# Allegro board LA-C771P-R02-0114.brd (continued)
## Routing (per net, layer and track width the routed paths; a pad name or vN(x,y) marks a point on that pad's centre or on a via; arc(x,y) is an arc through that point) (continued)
+1.8VALW: length 342.5
  TOP w0.305: v3(119.49,72.55) RC81.2
  TOP w0.381: CW4.1 99.98,15.5 99.89,15.59 UW2.1
  TOP w0.508: 50.2,70.6 49.49,71.31 48.34,71.31 48.19,71.15 48.18,71.15 47.62,70.59 47.62,70.58 47.56,70.52 47.56,68 47.17,67.62 47.17,64.68 51.25,60.6 52.49,60.6 55.19,57.9 55.19,57.72 55.19,57.35 58.88,53.66 58.88,48.12 58.25,47.48 v3(57.41,47.48) 56.45,47.48 55.66,48.27 RC52.1 ; 122.69,72.57 125,70.26 125,63.23 137.78,50.45 v3(139,50.45) ; 122.69,72.57 123.22,73.11 123.22,73.75 122.29,74.68 RC28.2 121.07,74.53 RC29.2 ; 122.69,72.57 v3(122.03,72.57) ; v3(57.01,46.28) 57.25,46.28 57.67,45.86 RC50.1 ; CC22.1 56.04,38.87 55.53,39.38 55.07,39.38 54.83,39.14 UC10.8 ; CC22.1 56.45,38.9 56.45,39.15 57.31,40.01 RC51.1 60.74,40.27 66.2,34.81 72.8,34.81 75.03,32.58 v3(75.03,32.27) RB13.1 ; CC22.1 56.42,38.26 v3(56.22,38.06) ; 87.92,32.5 87.92,31.12 88.12,30.92 88.12,29.12 QC2.2 ; 87.92,32.5 88.73,33.31 v2(91.96,33.31) 97.9,33.31 100.38,30.83 v3(101.6,30.83) 102.27,30.16 102.27,17.36 v3(102.32,17.31) 101.85,17.31 101.6,17.05 RW5.1 101.6,16.47 100.97,15.84 100.97,15.71 100.96,15.7 CW4.1 ; 87.92,32.5 87.53,32.89 87.53,33.55 87,34.07 85.35,34.07 82.68,31.4 v3(82.68,30.84) 82.57,30.73 82.57,29.9 83.52,28.96 RB7.2 ; v3(157.89,37.98) 160.82,37.98 161.7,37.09 v3(169.56,37.09) ; RW8.1 v3(93.88,17.15)
  IN1 w0.508: v3(157.89,37.98) 157.89,37.98 157.89,38.35 150.41,45.83 144.33,45.83 139.71,50.45 v3(139,50.45)
  IN2 w0.305: v3(119.49,72.55) 119.49,72.62 119.94,73.08 120.94,73.08 121.44,72.57 v3(122.03,72.57)
  IN2 w0.508: v3(102.32,17.31) 102.32,17.28 102.19,17.15 v3(93.88,17.15) ; v3(157.89,37.98) 158.88,36.99 158.88,29.2 155.35,25.66 154.67,25.66 v3(154.59,25.59) ; v3(57.41,47.48) 57.01,47.08 v3(57.01,46.28) ; v3(75.03,32.27) 75.64,31.66 81.87,31.66 v3(82.68,30.84)
  BOTTOM w0.229: UC4.AA18 107.3,82.38 107.3,82.93 106.71,83.52 v3(106.71,84.71)
  BOTTOM w0.254: UC4.N20 103.4,80.52 v3(103.4,80.37)
  BOTTOM w0.305: RC59.1 90.62,84.13 v3(91.22,84.13) 91.78,84.13 RC61.1
  BOTTOM w0.508: RM19.2 170.21,79.54 169.56,78.88 v3(169.56,37.09) ; v3(87.91,84.34) 88.16,84.59 RC38.1 ; v3(57.01,46.28) 55.84,45.11 55.84,38.43 v3(56.22,38.06) ; v3(154.59,25.59) 152.64,25.59 151.37,24.32 126.86,24.32 120.64,30.53 102.59,30.53 102.29,30.83 v3(101.6,30.83) ; CC61.1 95.8,82.56 v3(96.18,82.94) ; RC36.2 90.5,85.38 90.5,85.37 v3(91.07,85.37) 91.69,85.37 RC35.1
  vias: v3(51.34,70.7) v3(51.37,70.09) v3(51.37,69.48) v3(72.39,75.01) v3(72.41,74.36) v3(72.39,73.69) v3(73.04,73.69) v3(73.12,75.01) v3(73.07,74.36) v3(85.43,79.89) v3(86.14,79.89) v3(86.24,81.67) v3(86.85,81.67) v3(95.71,83.4) v3(104.78,78.42)
+1.8VALWP: length 5.3
  TOP w0.254: 69.05,71.06 69.05,70.9 68.49,70.34 v2(68.43,70.34) 66.29,70.34 65.49,71.14 PC604.1 PR603.1
+1.8VS: length 280.9
  TOP w0.381: v3(81.31,71.34) 82.67,69.98 88.28,69.98 88.83,69.43 v3(89.09,69.43) 91.84,72.18 97.88,72.18 98.84,73.14 102.2,73.14 RC9.2 102.87,73.25 104.64,73.25 104.91,72.98 v3(104.91,72.6) ; 18.12,95.97 18,96.08 14.82,96.08 14.47,95.73 14.47,95.19 14.03,94.75 RY2.1
  TOP w0.508: v3(60.22,81.15) 59.98,80.9 55.23,80.9 v3(55.08,81.06) ; 130.54,74.59 130.56,74.56 130.56,66.2 v3(129.88,65.51) ; v3(114.53,71.74) 114.54,71.73 114.54,68.69 v3(114.46,68.61) ; v3(81.31,71.34) 81.53,71.56 UC7.5 ; v3(126.19,74.56) 123.91,74.56 122.01,76.46 RC21.1 ; v3(74.69,75.3) 74.8,75.19 75.69,75.19 76.79,76.29 UC8.5
  TOP w0.762: 129.34,91.6 128.43,91.6 127.97,92.06 125.84,92.06 124.67,90.89 124.67,87.21 128.5,83.37 v3(128.5,81.18) 128.5,78.65 130.54,76.62 130.54,74.59 v3(130.54,74.59)
  IN1 w0.406: 112.91,68.06 112.1,68.06 111.16,69 111.16,69.68 110.17,70.67 109.58,70.67 108.19,72.07 106.74,72.07 106.65,71.98 105.4,71.98 104.88,72.5 104.88,72.6 v3(104.91,72.6) ; 112.91,68.06 112.99,68.06 113.55,68.61 v3(114.46,68.61) ; 112.91,68.06 112.91,67.32 114.92,65.31 117.27,65.31 117.98,64.6 120.8,64.6 121.23,65.03 v3(123.81,65.03)
  IN1 w0.508: v3(129.88,65.51) 126.04,65.51 125.56,65.03 v3(123.81,65.03) ; v3(130.54,74.59) 130.31,74.59 129.83,75.07 126.42,75.07 126.19,74.84 v3(126.19,74.56)
  IN1 w1.016: 23.91,93.63 24.87,94.6 35.01,94.6 37.17,96.76 49.97,96.76 52.31,94.42 52.31,91.65 51.19,90.53 v3(51.19,88.5) 52.28,87.41 55.23,87.41 57,85.63 ; 121.37,100.67 87.22,100.67 84.09,97.54 78.01,97.54 74.84,94.37 72.17,94.37 71.56,93.76 71.56,91.2 69.92,89.56 66.17,89.56 65.37,88.76 62.19,88.76 60.16,86.72 58.1,86.72 57,85.63 ; 57,85.63 57,84.9 54.62,82.51 54.62,82.03
  BOTTOM w0.254: UC4.U38 105.34,72.17 v3(104.91,72.6) ; RPY1.3 18.05,89.59 18.05,90.09 18.19,90.23 v3(18.75,90.23) 18.77,90.22 18.77,90.04 18.55,89.82 RPY1.4
  BOTTOM w0.508: RX3.1 50.25,88.09 50.66,88.5 v3(51.19,88.5) ; v3(55.08,81.06) 54.91,80.9 UC5.5 ; RC22.1 125.51,74.74 125.58,74.81 RC79.2 125.94,74.81 v3(126.19,74.56) ; v3(123.81,65.03) CC71.1 CC70.1 CC69.1 CC74.1 ; UC6.5 v3(60.22,81.15) ; v3(128.5,81.18) 128.33,81.36 RC82.2 ; v3(89.09,69.43) 89.14,69.48 CC67.1 ; RC14.1 91.3,75.09 85.06,75.09 v3(81.31,71.34) 78.83,71.34 74.88,75.3 v3(74.69,75.3)
  vias: v2(31.96,48.99) v3(18.83,95.72) v3(18.83,95.13) v3(22.39,92.9) v3(22.97,92.87) v3(23.78,32.39) v3(24.37,32.55) v3(32.82,22.79) v3(33.4,22.79) v3(54.41,76.13) v3(55.1,76.16) v3(114.34,74.79) v3(122.47,100.5) v3(123.24,100.5) v3(129.42,88.34) v3(129.39,87.66)
+1.8VS_AVDD2: length 4.6
  TOP w0.203: UA1.40 29.4,23.48 v3(29.47,23.4)
  TOP w0.508: v3(29.47,23.4) 29.47,23.28 30.01,22.74 CA9.1 30.77,22.74 RA5.1
+1.8VS_OUT:
  vias: v2(55.71,70.35)
+1.35V: length 119.1
  TOP w0.635: RD1.1 69.15,50.93 68.42,51.66 61.95,51.66 55.94,57.67 55.94,58.56 51.8,62.7 51.8,63.74
  TOP w1.016: RD1.1 77.41,48.18 79.74,50.5 90.03,50.5
  BOTTOM w0.254: v3(97.52,43.49) 98.02,43.49 98.48,43.95 98.48,45.37 98.93,45.82 JDIMM1.99
  BOTTOM w0.305: v3(103.08,44.51) 102.53,45.05 102.53,45.81 102.53,45.82 JDIMM1.111 ; JDIMM1.88 v3(95.63,39.98) ; v3(94.95,44.43) 95.1,44.43 95.49,44.81 95.49,45.58 95.33,45.73 JDIMM1.87 ; v3(97.43,39.95) JDIMM1.94 ; v3(106.13,40.64) 106.13,40.59 106.43,40.29 JDIMM1.124 ; 97.13,44.92 96.93,44.71 v3(96.43,44.71) ; 97.13,44.92 JDIMM1.93 ; 97.13,44.92 97.31,44.73 v3(97.62,44.73) ; v3(104.44,44.1) 104.37,44.1 103.92,43.65 103.92,43.19 103.38,42.65 v3(103.38,40.82) 102.83,40.27 JDIMM1.112 ; JDIMM1.75 91.73,45.78 90.51,44.56 v3(89.97,44.56)
  BOTTOM w0.356: v3(104.63,40) JDIMM1.118 ; v3(96.75,41.66) 98.41,41.66 99.23,40.84 JDIMM1.100 ; v3(106.61,45.22) 106.13,45.7 JDIMM1.123 ; JDIMM1.82 93.83,40.19 93.33,40.7 v3(93.22,40.7) 93,40.7 92.39,41.31 92.39,41.69 92.79,42.1 v3(93.1,42.1) ; JDIMM1.105 100.73,45.52 100.31,45.1 100.31,43.77 99.89,43.35 99.56,43.35 v3(99.55,43.36) ; v3(92.44,44.63) 92.69,44.63 93.53,45.47 JDIMM1.81 ; JDIMM1.117 104.33,45.41 104.3,45.38 v3(104.3,45.34) ; v3(95.64,41.36) 95.21,41.36 94.7,41.87 94.7,44.18 v3(94.95,44.43) ; v3(91.37,40.67) 91.6,40.67 92.03,40.24 JDIMM1.76 ; v3(100.87,40.26) 100.87,40.21 101.03,40.05 JDIMM1.106
  BOTTOM w0.508: RC6.1 117.89,61.19 117.49,60.79 117.49,60.44 CC31.2 116.82,60.44 CC32.2 116.8,59.98 117.13,59.65 117.13,56.52 122.56,51.09 v3(122.56,51.1)
  vias: v2(122.17,34.79) v3(93.07,35.95) v3(93.78,34.57) v3(94.77,35.92) v3(95.89,34.5) v3(96.98,35.87) v3(97.9,34.42) v3(99.04,35.31) v3(99.85,34.5) v3(101.02,35.26) v3(101.76,34.32) v3(102.62,35.26) v3(103.74,34.45) v3(104.73,35.31) v3(138.34,39.3) v3(138.34,38.54) v3(138.34,37.78) v3(138.34,37.01) v3(138.39,34.11) v3(138.39,33.34) v3(138.39,32.58) v3(138.39,31.82) v3(139.1,39.3) v3(139.1,38.54) v3(139.1,37.78) v3(139.1,37.01) v3(139.16,34.11) v3(139.16,33.34) v3(139.16,32.58) v3(139.16,31.82)
+1.35V_SOC: length 31.7
  IN2 w0.508: v3(120.1,68.67) 119.53,69.25 118.63,69.25 116.85,71.03 113.52,71.03 112.83,71.72 112.81,71.72 v3(112.81,71.71)
  BOTTOM w0.254: v3(98.97,66.34) 98.97,65.84 UC4.C51 ; v3(118.57,66.45) 118.95,66.83 UC4.BD49 ; UC4.A48 97.3,67.16 v3(97.19,67.04) ; UC4.F49 100.36,66.88 v3(100.77,67.29) ; UC4.F52 100.36,65.08 UC4.F53 100.36,64.1 v3(99.89,63.63) ; v3(118.72,63.76) 118.72,64.41 UC4.BD53 118.94,65.08 UC4.BD52 ; UC4.AV41 UC4.AV42 115.98,69.83 v3(115.57,69.42) ; UC4.BG51 120.27,65.78 v3(119.75,65.78) ; UC4.H46 101.71,68.69 v3(101.83,68.69) ; UC4.BB46 117.62,68.33 117.5,68.2 117.5,68.18 v3(117.49,68.18) ; UC4.D44 99.74,68.88 v3(99.74,68.63) ; UC4.AK38 112.4,72.1 112.81,71.69 112.81,71.71 ; v3(122.53,67.13) 122.51,67.16 UC4.BJ48 ; UC4.AM38 113.18,72.08 112.81,71.71 ; UC4.BF44 119.82,68.96 v3(120.1,68.67) ; 112.81,71.71 v3(112.81,71.71)
  BOTTOM w0.381: CC36.2 92.64,66.43 v3(92.62,66.45) ; CC35.2 99.7,59.47 v3(99.85,59.61) ; RC69.2 120.94,60.66 120.94,63.07 v3(121.19,63.33)
  BOTTOM w0.508: CC33.2 119.46,61.98 118.72,62.73 v3(118.72,63.76) ; v3(122.53,67.13) 123.62,66.05 CC34.2
  vias: v3(102.82,70.15) v3(107.73,71.48)
+1.35VP: length 46
  TOP w0.508: v3(141.92,38.85) v2(146.4,38.85) 154.54,38.85 155.81,37.58 155.81,36.79 159.11,33.49 159.11,27.92 157.98,26.79 PR406.1
  IN2 w0.254: v3(154.68,33.85) 154.95,34.13 154.95,36.26 152.97,38.23 143.09,38.23 v3(142.5,37.64)
  BOTTOM w0.254: PR407.2 v3(154.68,33.85) 154.47,33.65 PU303.5
+1.35VS: length 84.2
  TOP w0.381: v3(107.3,79.35) 107.5,79.35 108.18,80.04 CC42.1 ; v3(109.67,81.61) 109.88,81.83 CC41.1 109.88,83.25 CC40.1
  TOP w0.508: v3(91.26,95.33) 91.26,96.57 93.81,99.12 104.55,99.12
  IN1 w0.508: v3(89.89,93.23) 92.17,93.23 92.97,92.42 92.97,89.33 92.2,88.56 92.2,85.1 92.31,85
  IN1 w0.762: 54.47,63.86 54.47,64.59 56.14,66.26 56.14,69.28 56.65,69.78 57.33,69.78 61.7,74.15 62.63,74.15 67.57,79.09 68.6,79.09 71.2,81.7 73.76,81.7 74.79,82.73 81.22,82.73 81.83,83.34 85.5,83.34 87.54,85.38
  BOTTOM w0.203: UC4.AA25 107.3,78.6 v3(107.3,79.35)
  BOTTOM w0.254: v3(108.86,73.25) 109.21,72.9 UC4.AD36 ; v3(110.44,74.8) 110.81,75.18 UC4.AG32 ; UC4.U36 105.35,72.9 v3(105.73,73.29) UC4.V36
  BOTTOM w0.508: CC48.1 105.88,91.57 v3(106.02,91.57) ; v3(91.26,95.33) 90.58,94.65 RC43.1 90.01,94.5 89.7,94.18 89.7,93.42 v3(89.89,93.23) ; CC47.1 92.95,82.97 CC49.1 94.43,82.97 v3(94.47,83.01)
  vias: v2(115.2,99.46) v3(54.16,62.77) v3(54.74,62.77) v3(107.76,90.93) v3(108.23,90.51) v3(120.6,95.05) v3(121.28,95.02)
+1.35VS_OUT:
  vias: v2(54.34,66.35)
+3V_HDD: length 9.2
  BOTTOM w0.102: v2(208.57,45.75) 208.76,45.56 JHDD1.9 ; JHDD1.8 208.86,44.29 v2(208.49,43.93) ; v2(208.52,47.52) 209.2,46.83 JHDD1.10
+3V_HUB: length 17.9
  TOP w0.254: US2.20 194.95,55.41 CS9.1
  TOP w0.508: RS14.1 RS12.1 188.73,57.98 v3(188.68,57.92) 188.27,57.92 187.87,57.51 v2(187.87,57.21) 187.87,54.87 188.25,54.49 189.01,54.49 189.59,55.08 RS13.1 ; CS9.1 195.49,55.38 v3(195.49,55.91)
  IN1 w0.508: v3(195.49,55.91) 194.42,56.98 192.01,56.98 191.07,57.92 v3(188.68,57.92)
+3V_LAN: length 1.8
  BOTTOM w0.203: v3(34.68,71.66) 35.07,71.27 UL1.11
  BOTTOM w0.508: v3(38.44,62.59) 38.72,62.87 RL4.2
  vias: v2(37.8,64.52) v3(32.31,65.08) v3(32.95,65.22) v3(33.99,72.32) v3(33.97,71.71) v3(38.62,67.19) v3(38.82,67.75)
+3VALW: length 288.3
  TOP w0.508: v3(201.02,96.02) v2(201.02,93) 201.02,89.27 v3(199.93,88.17) ; RC27.2 83.31,78.39 v3(82.79,78.92) ; v3(71.41,32.27) 71.29,32.15 RB27.1 ; v3(69.07,32.77) 68.93,32.63 RB2.1 ; v3(85.86,29.46) 85.86,26.68 86.57,25.97 v3(86.57,25.03) ; v3(73.6,78.68) 73.6,78.68 73.6,81.17 75.29,82.85 77.15,82.85 v2(78.62,84.33) 79.39,85.1 84.74,85.1 87.56,87.92 87.56,89.95 88.93,91.32 88.93,94.23 89.22,94.51 92.59,94.51 92.89,94.81 v3(92.89,95.25) 92.89,96.42 94.26,97.8 100.68,97.8 101.25,97.23 RC76.2
  IN1 w0.508: 158.45,58 151.16,58 150.6,58.56 150.6,62.65 149.79,63.46 v3(148.87,63.46) ; 158.45,58 159.98,58 160.61,58.63 160.61,62.12 161.95,63.46 v3(162.79,63.46) ; 158.45,58 158.45,53.03 161,50.48 168.31,50.48 174.23,56.4 174.23,86.79 175.06,87.61 181.03,87.61 182.76,89.34 192.06,89.34 198.74,96.02 v3(201.02,96.02)
  IN1 w1.016: 33.84,89.04 37.24,89.04 39.99,91.78 39.99,94.01 41.46,95.49 43.98,95.49 46.85,92.62 46.85,88.76 48.78,86.83 49.74,86.83 51.45,85.12 51.45,78.33 52.97,76.81 52.97,76.71 52.97,76.45 52.97,76.45 52.97,73.82 55.13,71.66 55.13,66.68 53.27,64.83 53.27,61.3 ; v3(199.93,88.17) 199.93,87.97 205.62,82.28 205.62,69.02 203.64,67.04 203.64,60.66 207.83,56.47 207.83,48.22
  IN2 w0.508: v3(85.86,29.46) 85.86,29.7 85.45,30.11 84.11,30.11 83.43,29.43 74.92,29.43 72.09,32.27 v3(71.41,32.27) 71.13,31.99 70.11,31.99 69.33,32.77 v3(69.07,32.77)
  BOTTOM w0.381: v3(92.89,95.25) 93.14,95 UC9.5
  BOTTOM w0.508: PR729.2 149.62,63.46 149.62,63.46 v3(148.87,63.46) ; PR712.1 162.79,63.46 v3(162.79,63.46)
  vias: v2(59.04,56.57) v3(32.85,88.93) v3(32.82,88.3) v3(57.18,58.61) v3(57.19,58.02) v3(57.82,58.61) v3(57.82,57.97) v3(58.45,58.58) v3(58.48,57.97) v3(72.24,77.99) v3(72.26,78.64) v3(72.95,78.62) v3(72.92,77.97) v3(73.6,77.97) v3(189.44,23.68) v3(189.44,22.31) v3(189.46,22.97) v3(189.47,21.62) v3(190.15,23.68) v3(190.15,22.97) v3(190.15,22.31) v3(190.15,21.62) v3(190.86,23.63) v3(190.86,22.97) v3(190.86,22.28) v3(190.86,21.62) v3(198.97,88.32) v3(202.47,14.87) v3(203.11,14.87) v3(203.74,14.87) v3(204.33,14.87) v3(205.68,40.51) v3(205.68,39.85) v3(205.7,39.17) v3(205.68,38.5) v3(205.68,37.84) v3(205.7,37.18) v3(205.68,36.44) v3(206.44,40.51) v3(206.44,39.85) v3(206.41,39.16) v3(206.44,38.5) v3(206.44,37.84) v3(206.44,36.44) v3(206.46,37.18)
+3VALW_EC: length 59.9
  TOP w0.508: RW3.1 92.06,17.13 91.62,16.69 91.62,15.91 v3(91.42,15.71) ; 83.97,21.21 84.73,21.98 85.76,21.98 85.96,22.18 v3(85.96,23.07) 86.37,23.07 86.7,22.74 86.7,20.69 87.94,19.44 87.94,16.92 87.71,16.69 87.71,15.93 v3(87.56,15.78) ; 83.97,21.21 RB5.2 ; 83.97,21.21 84.52,20.67 84.52,19.77 83.72,18.98 RB20.2 ; RB18.1 69.83,31.58 68.93,30.67 RB2.2 68.93,30.64 ; v3(81.69,15.32) 81.69,15.07 82.76,14 RB21.2
  IN2 w0.508: v3(85.96,23.07) 85.93,23.07 85.84,22.97 80.37,22.97 79.89,22.48 77.91,22.48 76.56,21.14 74.99,21.14 74.43,20.58 72.17,20.58 70.39,22.36 68.95,22.36 66.83,24.48 65.75,24.48 64.75,25.48 64.75,27.87 v3(63.18,29.45)
  BOTTOM w0.508: v3(81.69,15.32) 82,15.63 87.41,15.63 v3(87.56,15.78) 87.84,16.06 89.92,16.06 90.28,15.71 v3(91.42,15.71)
  vias: v2(78.41,5.46) v3(53.91,32.24) v3(53.93,31.58) v3(62.47,30.06)
+3VALW_SOC: length 19.5
  TOP w0.305: v3(104.04,80.38) 104.04,80.98 CC81.1 103.99,81.1 103.99,82.25 104.03,82.29 v3(104.03,82.3) 104.13,82.39 104.13,83.77 103.42,84.48 103.42,85.99 103.33,86.08 103.33,87.29
  TOP w0.508: 103.33,87.29 103.06,87.56 103.06,89.77 103.28,89.99 v2(103.28,93.51) 103.16,93.63 103.16,94.29 103.28,94.42 CC83.1 CC79.1 101.26,95.18 RC76.1
  BOTTOM w0.254: v3(104.04,80.38) 104.04,80.18 UC4.N22
  BOTTOM w0.381: UC4.N18 103.74,82.01 v3(104.03,82.3) 104.45,81.87 UC4.P18
+3VALWP: length 27.3
  TOP w0.508: v2(189.9,42.86) 189.9,42.05 v3(189.99,41.96)
  IN2 w0.254: v3(201.55,40.79) 201.55,40.8 200.41,41.94 193.86,41.94 193.39,42.41 190.88,42.41 190.42,41.96 v3(189.99,41.96)
  IN2 w0.381: v3(201.47,39.92) 199.97,41.43 193.61,41.43 193.07,41.97 191.14,41.97 190.69,41.52 190.69,41.08 v3(190.82,40.95)
  BOTTOM w0.254: PR302.2 v3(189.99,41.96) ; v3(190.82,40.95) 190.91,40.86 PU301.4
+3VDD_CODEC: length 11.8
  TOP w0.203: UA1.36 26.97,21.08 27.22,20.84 v3(27.97,20.84)
  IN2 w0.508: v3(27.97,20.84) 27.97,21.09 26.96,22.11 26.96,27.81 v3(27.69,28.54)
  BOTTOM w0.508: v3(27.97,20.84) 28.54,20.27 29.62,20.27 CA18.2
+3VLP: length 526.9
  TOP w0.203: UB1.111 80.99,19.37 81.18,19.56 ; UA1.20 20.82,23.88 v3(20.73,23.79)
  TOP w0.508: v3(166.78,38.24) 176.33,38.24 v2(178.26,40.17) 178.26,59.62 v3(182.41,63.76) ; 81.18,19.56 81.52,19.9 82.42,19.9 CB7.1 v3(82.5,20.5) ; v3(86.58,29.51) 86.51,29.43 86.51,26.93 87.42,26.02 87.42,20.88 88.58,19.72 v3(88.58,19.29) 88.58,16.66 88.35,16.43 88.35,15.22 92.77,10.8 94.75,10.8 95.71,9.84 v3(95.71,8.87) ; v3(79.05,2.96) 79.54,3.44 79.54,6.11 82.07,8.65 RB4.1 ; v3(166.78,28.76) 166.01,28.76 v3(157.45,20.2) ; R7.2 v3(21.49,7.12) ; v3(189.09,41.92) 189.09,41.74 190.58,40.24 PR314.1 ; R3.2 28.76,90.23 v3(29.37,89.62) ; R16.2 v3(12.28,11.54) ; RB6.2 83.72,27.73 84.17,28.18 84.17,29.2 83.24,30.13 v3(83.24,30.36) ; v3(76.58,30.23) 76.58,31.15 76.15,31.57 RB11.1
  IN1 w0.508: v3(196.98,66.37) 194.38,63.76 v3(182.41,63.76) 180.65,65.52 180.65,81.98 182.65,83.98 193.94,83.98 v3(197.39,87.43) ; v3(37.79,7.97) 37.79,10.99 38.92,12.12 38.92,24.8 v3(36.1,27.62) 36.1,29.98 33.56,32.52 33.56,45.79 41.05,53.29 41.05,72.55 38.56,75.04 36.61,75.04 29.5,82.15 29.5,89.49 v3(29.37,89.62)
  IN2 w0.508: v3(182.41,63.76) 184.44,61.73 186.47,61.73 187.74,60.46 187.74,54.47 188.3,53.91 188.3,52.15 188.69,51.76 188.69,49.6 187.74,48.65 187.74,45.55 189.09,44.2 v3(189.09,41.92) ; v3(21.49,7.12) 16.7,7.12 v3(12.28,11.54) ; v3(86.58,29.51) 86.58,29.93 85.77,30.74 83.62,30.74 v3(83.24,30.36) 83.04,30.16 82.46,30.16 81.59,31.02 77.36,31.02 v3(76.58,30.23)
  BOTTOM w0.508: PR222.2 v3(196.98,66.37) ; v3(21.49,7.12) 22.34,7.97 v3(37.79,7.97) 39.6,6.15 59.65,6.15 60.28,5.52 62.54,5.52 63.58,4.48 72.85,4.48 74.38,2.96 v3(79.05,2.96) 79.05,5.8 82.05,8.8 83.27,8.8 83.78,9.31 92.77,9.31 93.78,8.29 95.13,8.29 v3(95.71,8.87) ; v3(36.1,27.62) 34.19,29.53 26.5,29.53 24.72,27.75 23.05,27.75 22.33,27.03 22.33,24.49 21.63,23.79 v3(20.73,23.79) ; v3(197.39,87.43) 200.23,87.43 200.95,88.15 PR107.2 ; v3(166.78,38.24) v3(166.78,28.76) 166.78,14.15 161.86,9.23 127.26,9.23 120.32,16.16 115.98,16.16 113.88,18.27 109.61,18.27 109.26,17.92 91.57,17.92 90.38,19.11 88.76,19.11 v3(88.58,19.29) 87.46,19.29 87.03,19.72 83.14,19.72 82.5,20.36 v3(82.5,20.5) ; v3(157.45,20.2) 155.17,17.92 PR115.2
+3VS: length 438.6
  TOP w0.254: v3(143.06,44.81) 143.11,44.76 145.07,44.76 146.11,45.81 146.11,48.24 139.38,54.97 137.43,54.97 128.86,63.54 128.86,74.9 127.33,76.44 v3(125.66,76.44) 125.66,76.88 127.03,78.25 127.03,82 v3(126.73,82.3) 126.52,82.3 125.71,81.49 124.19,81.49 122.94,80.24 122.16,80.24 121.78,80.62 RC77.2 ; RPB1.3 71.21,5.69 v3(71.46,5.44) 71.7,5.69 RPB1.4 ; 43.82,12.55 43.92,12.65 43.92,13.37 44.28,13.73 UR1.9 ; v3(129.42,48.21) 128.73,47.52 CD19.1
  TOP w0.381: v3(15.4,97.4) 15.4,97.29 15.6,97.09 QY1.5
  TOP w0.508: v3(98.51,5.44) 98.51,8.82 95.66,11.67 93.22,11.67 90.71,14.18 RW1.2 90.71,18.34 91.52,18.34 91.73,18.14 RW4.1 ; RA15.2 v3(13.75,24.82) ; v3(52.79,4.76) 52.79,11.33 RR8.2 ; v3(156.45,37.5) 160.46,33.49 160.46,31.45 162.34,29.57 169.6,29.57 171.99,27.19 ; v3(221.06,93.09) 220.68,92.71 R1.1 ; v3(68.26,82.93) 68.26,81.73 67.95,81.42 PR602.1 67.46,83.4 68.17,84.11 70.95,84.11 71.82,83.24 74.78,83.24 75.51,83.97 76.28,83.97 77.41,85.1 77.41,86.03 ; v3(62.57,77.52) 62.57,71.45 63.91,70.1 65.16,70.1 65.89,69.38 67.92,69.38 68.01,69.29 73.62,69.29 77.74,73.41 77.74,74.87 77.91,75.04 ; RC25.1 163.61,90.18 169,84.78 173.45,84.78 174.57,85.9
  TOP w0.762: 46.39,99.48 46.26,99.35 37.07,99.35 35.9,98.19 33.76,98.19 32.81,97.24 v3(32.81,95.6) 32.81,94.37 33.62,93.56 36.58,93.56 37.55,92.59
  TOP w1.524: 66.68,96.58 71.05,96.58
  TOP w1.778: 75.95,89.21 75.75,89.42 75.75,92.63 76.54,93.42 76.54,95.02 75.49,96.06 75.49,96.78
  IN1 w0.381: v3(32.81,95.6) 23.23,95.6 22.64,96.19 20.02,96.19 18.93,97.29 15.51,97.29 v3(15.4,97.4)
  IN1 w0.508: v3(62.57,77.52) 66.42,81.38 66.71,81.38 v3(68.26,82.93) ; v3(53.63,88.93) 53.63,91.86 53.2,92.29 v3(53.2,96.25) ; v3(221.06,93.09) 220.47,92.5 214.98,92.5 213.29,94.19 198.05,94.19 192.41,88.55 183.07,88.55 179.64,85.12 177.22,85.12 ; v3(31.88,80.98) 37.02,75.85 38.65,75.85 41.79,72.71 41.79,71 42.65,70.14 42.65,69.45 v3(41.74,68.54) ; v3(143.06,44.81) 143.04,44.84 150.5,44.84 155.78,39.56 155.78,38.16 v3(156.45,37.5)
  IN1 w1.778: 177.22,85.12 176.49,84.39 176.49,51.2 179.03,48.66 179.03,25.1 182.43,21.7
  IN2 w0.254: v3(143.06,44.81) 140.57,47.3 133.61,47.3 132.7,48.21 v3(129.42,48.21)
  BOTTOM w0.254: v3(125.66,76.44) 125.69,76.41 125.69,75.79 RC78.2 ; RC68.2 v3(126.73,82.3) ; JDIMM1.199 128.93,47.73 v3(129.42,48.21)
  BOTTOM w0.508: v3(53.63,88.93) 53.63,87.13 52.61,86.11 50.5,86.11 CX10.2 51.06,87.08 QX2.3 ; v3(13.75,24.82) 13.75,25.54 14.54,26.32 14.54,27.97 19.79,33.23 22.61,33.23 23.93,34.55 30.49,34.55 v3(30.89,34.96) ; v3(41.74,68.54) 41.7,68.5 RL2.1
  vias: v2(30.42,75.17) v2(160.67,18.75) v2(166.64,25.22) v3(39.38,10.7) v3(39.38,9.99) v3(40.01,10.73) v3(40.01,9.99) v3(40.7,10.75) v3(40.7,10.02) v3(60.57,98.61) v3(61.27,98.61) v3(61.91,98.65) v3(73.9,5.06) v3(74.71,5.34) v3(119.08,6.79) v3(119.77,6.79) v3(120.48,6.79) v3(121.15,6.79) v3(121.79,6.76) v3(122.43,6.74) v3(123.15,6.77) v3(175.6,86.19) v3(175.68,85.56) v3(176.36,86.24) v3(176.39,85.61) v3(183.85,20.61) v3(183.85,19.87) v3(184.49,20.61) v3(184.49,19.9) v3(185.13,20.55) v3(185.15,19.9) v3(185.78,20.55) v3(185.79,19.92) v3(186.42,20.55) v3(186.48,19.92)
+3VS_1.8VS_SOC: length 15.3
  TOP w0.102: v2(125.6,77.48) 125.28,77.48 v3(124.46,76.66)
  IN1 w0.254: v3(124.46,76.66) 124.36,76.56 122.23,76.56 121.58,77.22 115.6,77.22 115.47,77.09 v3(114.33,77.09)
  BOTTOM w0.203: UC4.AM27 113.57,77.06 114.3,77.06 v3(114.33,77.09)
  BOTTOM w0.381: v3(124.46,76.66) 124.68,76.45 RC78.1 124.68,74.82 RC79.1
+3VS_CMOS:
  vias: v1(54.99,92.63)
+3VS_OUT:
  vias: v2(186.47,24.16)
+3VS_R_CMOS: length 7.7
  BOTTOM w0.102: v2(52.89,83.6) 52.89,84.36 54.14,85.61 QX2.1
  BOTTOM w0.508: RX10.1 54.64,89.97 CX11.1 54.64,88.25 55.05,87.84 55.05,87.03 QX2.1
+3VS_SOC: length 13.4
  TOP w0.102: v1(118.92,79.09) 119.09,79.09 v3(119.82,78.36)
  TOP w0.508: RC77.1 119.8,80.12 120,79.92 CC89.1 120,79.04 120.46,78.59 CC91.1 119.87,78.41 v3(119.82,78.36)
  IN1 w0.508: v3(119.82,78.36) 119.18,77.73 115.6,77.73 114.89,78.44 114.03,78.44 113.57,77.98 v3(113.57,77.83)
  BOTTOM w0.229: UC4.AN24 113.57,78.57 v3(113.57,77.83)
  BOTTOM w0.254: UC4.AN27 113.95,77.45 v3(113.57,77.83)
+3VS_TCM: length 16.7
  TOP w0.381: v3(90.74,25.53) CW3.1 91.65,26.17 91.67,26.15 UW1.19 ; v3(90.85,24.14) 90.73,24.02 CW2.1 91.39,22.87 91.42,22.9 UW1.24
  IN2 w0.508: v3(90.74,25.53) 90.85,25.42 v3(90.85,24.14)
  BOTTOM w0.508: v3(90.74,25.53) v2(93.61,25.53) 96.9,25.53 97.54,26.17 v3(99.71,26.17)
  vias: v3(91.52,19.23) v3(92.23,19.21) v3(99.55,18.86) v3(100.21,18.88)
+3VS_WLAN: length 7.2
  TOP w0.102: v2(153.27,91.22) 153.04,90.99 v3(153.04,90.09)
  BOTTOM w0.508: v3(172.12,89.55) 172.65,89.01 RM18.2 172.65,88.76 173.46,87.94 173.46,85.68 172.88,85.1 RM20.2
  vias: v2(171.82,91.12) v2(173.82,91.99) v3(153.63,90.09) v3(171.71,90.24) v3(172.37,90.24) v3(173.01,90.24)
+5V_HUB: length 10.2
  TOP w0.508: v3(202.73,56.52) RS10.1
  IN2 w0.508: v3(193.5,56.12) 193.91,56.52 v3(202.73,56.52)
+5V_ODD: length 15.2
  BOTTOM w0.102: v2(221.44,105.96) 221.44,106.4 222.91,107.86 224.56,107.86 224.86,108.16 JODD1.10 222.33,108.65 v2(221.38,107.7) ; v2(221.51,104.21) 221.51,105.03 223.87,107.39 225.6,107.39 JODD1.9
+5VALW: length 188.6
  TOP w0.203: UQ1.4 v3(190.35,25.4)
  TOP w0.508: PR405.1 155.58,25.48 v3(153.25,23.15) 152.41,22.31 v2(147.96,22.31) 134.5,22.31 v2(129.31,17.12) v2(121.74,9.55) 120.1,7.91 v3(120.1,7.91) ; PU601.6 67.65,79.24 68.92,80.5 PC601.1 v3(68.92,83.22) ; v3(162.87,48.35) 162.08,47.55 162,47.55 RQ5.2 160.16,46.95 159.19,45.98 158.45,45.98 157.71,46.72 RQ9.2
  IN1 w0.508: v3(68.92,83.22) 68.92,82.65 67.01,80.74 66.89,80.74 61.95,75.81 61.11,75.81 61.1,75.8 61.02,75.8 58.28,73.06 v3(56.61,73.06) ; v3(152.33,56.5) 152.33,56.5 152.33,54.8 153.63,53.5 157.08,53.5 162.24,48.35 v3(162.87,48.35)
  IN2 w0.508: v3(162.87,48.35) 162.77,48.24 162.77,29.62 156.29,23.15 v3(153.25,23.15) ; v3(36.1,49.67) 36.33,49.67 38.37,51.7 38.37,51.71 42.81,56.15 42.81,59.47 46.09,62.76 47.9,62.76 50.15,65.01 50.15,67.32 v3(50.31,67.48)
  BOTTOM w0.508: v3(162.87,48.35) 162.42,48.8 162.42,53.55 165.9,57.03 165.9,64.02 161.91,68 156.47,68 156.3,67.83 PR718.2 156.3,67.36 156.3,67.36 PR719.1 ; PR722.1 v3(152.33,56.5) ; v3(153.25,23.15) 155.58,25.48 PR405.1 ; v3(56.61,73.06) 56.18,72.63 55.41,72.63 50.31,67.53 v3(50.31,67.48)
  vias: v3(41.77,32.9) v3(41.77,32.17) v3(42.42,32.62) v3(42.4,31.94) v3(43.1,32.62) v3(43.05,31.91) v3(43.74,32.62) v3(43.69,31.91) v3(44.35,31.91) v3(44.4,32.62) v3(45.01,31.91) v3(45.06,32.62) v3(45.65,31.91) v3(45.7,32.62) v3(46.33,31.89) v3(46.38,32.6) v3(47.01,32.62) v3(46.96,31.91) v3(175.75,10.3) v3(176.08,11.36) v3(176.21,9.31) v3(176.69,10.32) v3(177.07,12.3) v3(177.07,11.36) v3(177.15,9.31) v3(177.71,10.35) v3(178.01,12.33) v3(178.11,11.34) v3(178.06,9.31) v3(178.65,10.32) v3(178.9,12.3) v3(179,11.34) v3(179.08,9.25) v3(179.59,10.35) v3(179.94,12.28) v3(179.97,11.31) v3(189.21,29.35) v3(189.21,28.66) v3(189.18,27.95) v3(189.85,29.4) v3(189.84,28.69) v3(189.82,27.97) v3(190.13,29.98) v3(190.3,52.23) v3(190.5,29.4) v3(190.48,28.71) v3(190.46,28) v3(190.66,53.53) v3(190.81,54.54) v3(190.81,29.98) v3(191.14,29.39) v3(191.12,28.71) v3(191.09,27.97) v3(191.45,29.96) v3(191.65,53.55) v3(191.83,29.39) v3(192.06,52.18)
+5VALWP: length 12.8
  BOTTOM w0.254: 47.83,46.34 47.63,46.54 47.51,46.54 46.75,47.3 PU302.4 ; PR309.2 48.22,43.85 48.22,40.93
  BOTTOM w0.381: 47.83,46.34 48.09,46.08 49.54,46.08 v2(49.83,45.79) 49.83,44.19 48.75,43.11 48.75,41
+5VDDA_CODEC: length 9.3
  TOP w0.203: 20.7,20.39 20.97,20.67 22.63,20.67 22.97,21.01 UA1.26
  TOP w0.762: 20.7,20.39 20.52,20.39 v2(19.57,19.45) 18.5,18.37 CA8.1 17.13,18.37 CA7.1 17.1,16.94 RA4.1
+5VS: length 246.7
  TOP w0.508: RB9.2 RB8.2 v3(74.96,7) ; v3(72.8,6.1) 72.8,6.11 RB12.2 ; v3(221.62,95.07) 221.62,94.66 220.59,93.62 R2.1 ; R14.2 v3(30.39,7.12)
  IN1 w0.508: v3(221.62,95.07) 221.62,97.61 223.46,99.46
  IN1 w1.016: 37.37,13.49 37.37,24.9 35.11,27.16 35.11,29.71 32.42,32.41 32.42,46.36 34.6,48.55 34.6,50.71 40.17,56.27 40.17,71.99 38.1,74.05 36.28,74.05 28,82.33 28,83.46 27.12,84.34 26.47,84.34 25.51,83.37 24.29,83.37 23.15,84.51 23.15,88.2 21.7,89.64 v3(20.71,89.64)
  IN1 w2.032: 224.19,99.35 224.19,93.57 221.73,91.11 214.4,91.11 212.91,92.59 198.61,92.59 192.03,86.01 182.71,86.01 178.95,82.25 178.95,60.89 182.84,57.01 182.84,48.09 181.47,46.72 181.47,32.6 183.04,31.02
  IN1 w2.921: 104.99,2.94 92.24,2.94 87.35,7.83 83.95,7.83 82.07,5.95 76.54,5.95
  vias: v2(182.29,36.27) v3(17.81,14.28) v3(17.84,13.45) v3(20.4,88.81) v3(35.39,12.25) v3(35.73,12.81) v3(35.72,11.67) v3(36.05,12.25) v3(36.43,11.67) v3(184.13,29.88) v3(184.82,30.62) v3(184.82,29.9) v3(185.31,31.03) v3(185.41,31.76) v3(185.47,30.39) v3(185.96,31.1) v3(186.06,31.8) v3(186.11,30.39) v3(186.62,31.1) v3(186.7,31.78) v3(186.8,30.39) v3(187.26,31.03) v3(187.51,30.39) v3(188.2,7.12) v3(188.81,6.41) v3(189.01,7.63) v3(189.54,6.92) v3(189.59,8.26) v3(190.23,7.48) v3(190.41,8.77) v3(190.99,7.96) v3(224.82,103.18) v3(224.82,102.44) v3(224.82,101.68) v3(224.8,100.97)
+5VS_HDD: length 8.9
  BOTTOM w0.102: JHDD1.16 v2(208.77,54.45) ; JHDD1.14 209.79,51.91 v2(208.66,50.78) ; JHDD1.15 209.28,53.18 v2(208.71,52.61)
+5VS_OUT:
  vias: v2(186.47,26.83)
+5VS_PVDD: length 5.2
  TOP w0.203: RA3.2 30.46,24.46 29.88,23.88 28.62,23.88 28.61,23.88 UA1.41 ; UA1.46 28.32,25.88 28.41,25.96 29.34,25.96
  vias: v3(29.04,27.06) v3(29.62,27.06)
+12.6VB_DDR: length 11.1
  TOP w0.254: 143.13,26.11 143.73,25.51 152.15,25.51 153.42,26.77 PR408.1
  vias: v2(141.37,28.32) v3(141.89,28.61) v3(141.86,27.95) v3(142.65,28.61) v3(142.62,27.95)
+AV12: length 1.5
  TOP w0.102: v2(42.6,16.67) 43.24,16.04 CR1.1
+DV12S: length 7.3
  TOP w0.102: CR3.1 43.9,7.48 v2(43.11,6.69)
  TOP w0.305: UR1.11 44.91,12.73 44.47,12.29 44.47,11.74
  TOP w0.508: 44.47,11.74 44.47,10.92 43.95,10.4 CR4.1 43.95,8.01 CR3.1
+DV33_18: length 6.8
  TOP w0.102: CR10.2 48.37,8.77 48.37,5.87 v2(48.88,5.37)
  TOP w0.254: UR1.15 47.18,10.52
  TOP w0.508: CR10.2 47.88,9.82 47.18,10.52
+V18R:
  vias: v2(81.41,25.05)
+VCC_LPC: length 1.8
  TOP w0.203: v2(75.18,29.53) 74.93,29.28 UB1.9
+VCC_SPI: length 2.1
  TOP w0.203: UB1.125 80.65,24.97 81.48,25.8
  vias: v2(81.44,26.88)
GND: length 2107.7
  TOP w0.102: C3.2 220.5,100.15
  TOP w0.127: v3(170.86,39.81) v2(169.91,39.81)
  TOP w0.203: UB1.35 64.1,25.37 62.81,25.37 v3(62.57,25.61) ; UB1.11 v3(74.13,29.04) ; v3(81.19,20.56) 81.19,20.56 80.8,20.17 UB1.113 ; v3(76.94,13.44) 77.33,13.06 UB1.94 ; v3(69.25,25.43) 68.93,25.75 UB1.24 ; UQ2.11 54.09,67.48 v3(54.24,67.62) ; UQ1.11 UQ1.15 v3(188.51,25.4)
  TOP w0.254: PU501.8 60.44,62.16 60.28,62.31 60.05,62.31 59.9,62.16 v3(59.9,61.8)
  TOP w0.305: v3(102.27,16.13) 101.63,15.5 CW4.2 ; v3(89.82,21.01) 90.15,20.68 CW1.2 ; CC5.1 82.07,77.38 83.05,76.41 UC7.3 ; CW2.2 v3(90.15,24.09)
  TOP w0.381: UW2.2 v3(100.18,16.24) ; v3(120.02,73.59) 119.89,73.46 RC32.1 ; v3(68.1,32.06) 67.92,31.87 CB4.2 ; v3(15.27,95.51) 15.02,95.26 15.02,94.9 QY1.1 ; UW1.4 v3(99.75,22.25) ; v3(104.86,83.94) 104.66,83.74 CC85.1 ; UW1.25 91.49,22.25 v3(91.35,22.11) ; v3(91.45,28.51) 91.69,28.75 UW1.15 ; v3(48.16,65.72) 48.26,65.81 CQ15.1 ; v3(108.08,74.78) 108.08,74.07 CC65.1 108.15,73.34 v3(108.1,73.29) ; v3(119.82,75.49) 119.79,75.47 CC62.1 ; CC14.2 97.49,79.71 97.17,79.39 v3(96.96,79.39) ; v3(90.07,25.56) 90.16,25.64 CW3.2 ; v3(99.73,24.24) 99.73,24.24 99.68,24.2 UW1.7 ; v3(101.99,82.22) 101.99,81.95 102.4,81.54 103.04,81.54 CC76.1 ; RC57.1 RC56.1 98.08,82.53 97.14,83.47 v3(97.14,83.58) ; v3(109.64,74.82) 109.61,74.79 CC46.2 108.99,75.49 CC44.2 ; CS12.1 189.09,56.22 188.7,56.6 v3(188.63,56.6) ; UW1.18 v3(93.99,26.8) ; v3(96.98,27.01) 97.19,26.8 UW1.11 ; v3(105.73,80.87) 105.14,80.87 CC81.2
  TOP w0.457: v3(151.95,84.46) 151.99,84.43 155.15,84.43 155.32,84.26 PH703.1 ; v3(104.21,71.66) 104.57,72.01 CC20.2
  TOP w0.508: CD19.2 128.72,45.95 RD5.1 127.82,45.16 v3(127.7,45.04) ; v3(129.42,36.86) 129.42,37.3 128.96,37.76 CD16.2 ; CR3.2 v3(41.53,7.97) ; CR1.2 v3(41.84,16.37) ; v3(111.41,3.46) 112.75,2.13 SW3.4 ; v3(14,6.99) 14.26,6.74 C9.2 ; CD12.2 v3(92.05,37.14) ; CQ20.2 v3(155.13,45.81) ; CQ12.1 CQ9.1 48.26,70.33 v3(48.45,70.52) ; v3(51.39,36.66) 51.53,36.52 CC26.1 ; CX2.2 73.95,87.72 v3(73.46,87.23) ; JPWRB1.2 27.98,93.33 v3(27.49,92.84) 26.98,93.35 JPWRB1.1 ; CQ4.2 v3(193.51,24.58) ; v3(70.02,44.64) 69.7,44.64 69.13,45.21 RD2.1 69.13,47.2 CD1.2 ; CB10.1 73.26,31.86 v3(73.73,32.33) 74.14,31.92 CB14.1 ; v3(84.74,25.79) CB11.2 83.51,26.32 CB13.1 ; D1.1 v3(219.65,99.47) ; v3(74.03,40.69) 73.89,40.69 72.93,39.73 CD2.2 ; v3(52.1,44.46) 51.02,45.54 UC10.4 ; C6.2 v3(221.14,102.24) ; CQ5.1 v3(183.83,27.03) ; v3(91.99,42.67) 90.91,43.74 CD15.2 ; v3(97.29,91.98) 97.29,91.98 CC93.2 ; v3(108.1,73.29) 108.1,73.13 108.54,72.69 CC29.2 108.55,72.57 RC3.1 ; v3(38.64,92.03) 38.83,91.84 38.83,90.5 JKB1.32 37.31,90.5 v3(36.99,90.18) ; CR9.2 47.88,6.99 v3(47.88,7.5) CR10.1 ; QY1.4 v3(16.88,96.74) ; v3(93.63,43.19) 93.38,43.44 CD8.2 ; PC603.2 PR604.2 v3(66.57,82.88) ; RB32.2 83.44,22.68 83.44,23.56 RB25.1 84,23.58 v3(84.39,23.96) ; v3(220.94,95) 220.46,94.52 C4.2 ; v3(215.43,97.42) 215.7,97.69 JTP1.4 ; CA10.2 28.17,31.66 v3(28.1,31.58) ; CC79.2 CC83.2 v3(103.28,98.2) ; v3(83.8,81.97) 83.8,82.49 83.5,82.78 CC16.2 ; v3(56.95,69.05) 56.88,68.97 CQ11.1 ; v3(187.68,53.12) 187.21,52.65 US3.2 ; CD7.2 107.42,47.5 v3(108.39,48.47) ; CC95.2 v3(122.05,96.95) ; RQ8.2 v3(166.68,42.81) ; v3(57.02,67.18) CQ14.1 56.26,66.34 CQ13.1 ; RR1.1 v3(41.69,13.33) ; v3(154.01,26.25) 154.5,26.74 PC408.1 ; v3(158.76,45.06) 158.76,45.05 Q5.3 ; RS11.2 v3(188.6,60.64) ; CC5.1 82.07,78.01 81.16,78.93 v3(81.16,79.55) ; RC33.1 121.98,75.54 v3(122.02,75.5) ; v3(151.86,90.05) 151.86,90.67 RM13.1 ; v3(107.75,39.91) 107.75,39.9 CD3.2 ; v3(16.28,93.13) 16.43,93.29 RY10.2 ; v3(96.68,95.77) 97.01,96.09 CC50.1 ; RA28.1 33.18,19.49 v3(33.18,19.97) ; v3(74.4,92.21) 74.4,91.43 JKB1.31 73.4,90.5 72.5,91.39 70.51,91.39 v3(70.44,91.32) ; CD5.2 v3(95.17,36.72) ; v3(13.87,93.73) CY10.1 ; RC62.1 104.3,96.09 RC55.2 104.3,96.27 v3(104.83,96.81) ; v3(60.9,25.58) 60.91,25.58 CB8.2 ; RA26.1 v3(30.01,13.27) ; CQ19.1 v3(154.8,54.63) ; D2.1 v3(28.53,84.54) ; v3(58.11,38.13) 57.37,38.87 CC22.2 ; v3(216.52,102.78) 216.33,102.59 JTP1.8 v3(214.4,104.32) ; J2.1 30.88,90.36 v3(31.04,90.51) C2.2 ; UC8.3 78.23,82.22 77.84,81.83 v3(77.84,80.78) ; CA4.1 31.91,27.06 v3(31.43,27.54) ; CQ8.1 v3(193.42,28.64) ; v3(83.41,20.53) 83.42,20.52 CB7.2 ; 97.42,48.78 v3(96.43,48.78) ; SW3.6 110.55,2.8 v3(109.94,3.41) ; v3(194.55,52.05) 193.94,51.44 CS10.2 190.25,51.44 190.25,51.42 v3(190,51.16) ; CS11.2 v3(201.07,57.29) ; PC211.1 196.44,74.68 v3(196.88,74.24) ; v3(160.51,43.11) 161.25,42.37 Q3.3 ; D4.1 v3(6.51,10.98) ; CQ16.1 50.27,64.68 50.27,63.76 50.38,63.66 v3(50.38,63.13) ; CY12.2 17.02,95.51 v3(16.54,95.51) ; CC91.2 121.95,78.99 v3(121.95,79.11) 121.53,79.53 CC89.2 ; CR2.2 v3(41.69,14.25) ; RC65.1 122.17,83.27 122.26,83.35 v3(122.26,83.37) ; CS6.2 186.01,54.9 v3(186.37,55.25) ; PC750.2 154.11,56.85 v3(154.45,56.51) ; UY1.2 v3(17.87,92.74) ; CR5.1 v3(42.17,10.06) ; v3(165.55,48.06) 165.55,48.05 Q2.3 ; v3(128.25,36.92) 128.25,37.25 128.77,37.76 CD16.2 ; v3(31.3,30.95) 31.19,30.84 CA2.2 CA1.2 ; CA12.1 v3(26.75,31.66) ; CR4.2 v3(42.3,9.05) ; CQ10.1 v3(57.03,68.08) ; v3(154.39,46.54) 154.35,46.58 Q4.3 ; CD11.2 104.93,48.27 104.43,48.77 v3(104.3,48.77) ; D3.1 v3(34.07,86.8) ; SW4.4 v3(184.5,2.66) ; UX1.2 72.98,85.46 v3(73.17,85.26) ; v3(100.46,48.07) 100.14,48.39 CD6.2 ; C1.2 220.97,91.79 221.94,92.76 v3(221.94,93.3) ; C5.2 220.57,101.07 v3(221.07,100.56) 220.65,100.15 220.5,100.15 ; SW3.3 v3(108.35,3.46) ; L4.1 67.55,5.65 v3(66.71,6.49) ; CQ18.1 v3(153.53,55.25) ; SW4.5 v3(183.72,6.27) ; C11.2 v3(25.32,90.48) ; CA3.2 v3(24.97,31.68) ; CD10.2 v3(102.52,36.81) ; RA24.1 v3(13.11,11.69) ; v3(131.6,46.89) 131.59,46.89 CD18.2 129.66,46.89 RD6.1 ; CB6.2 82.2,11.82 CB5.2 82.51,10.8 82.84,10.47 v3(82.84,9.99) ; CD14.2 v3(97.39,37.03) ; CQ1.1 v3(193.52,23.56) ; v3(94.42,48.9) 93.66,48.14 CD4.2 ; RA21.1 v3(15.65,27.31) ; CD13.2 v3(99.21,37.09) ; v3(109.2,6.1) 109.37,6.27 SW3.5 ; CD16.2 129.24,38.11 CD17.2 ; v3(220.9,105.77) 221.01,105.89 CO9.2 220.8,106.89 v3(220.14,106.89) ; SW4.6 v3(182.3,2.11) ; RO5.1 v3(226.85,103.38) ; CS9.2 v3(195.23,54.4) ; CC94.2 105.73,72.59 v3(105.72,72.57) ; CA22.1 v3(30.06,17.71) ; CB3.2 v3(61.08,28.04) ; SW4.3 v3(181.12,1.9) ; v3(126.47,96.68) 127.03,96.12 RC63.2 ; CQ6.1 v3(183.8,26.01) ; RA10.1 v3(33.79,28.46) ; CQ2.1 v3(183.83,25) ; CQ17.1 v3(165.15,48.82) ; v3(5.52,9.1) 5.09,8.67 SW5.2 ; CR6.1 v3(41.64,12.4) ; v3(14.66,17.66) DA3.1 ; C10.2 27.74,89.92 v3(28.8,88.86) ; v3(99.32,96.02) 99.95,96.02 CC86.1 ; CQ3.1 v3(183.78,23.98) ; CQ7.1 v3(193.45,26.61) ; RD4.1 v3(109,37.09) ; PC402.2 v3(141.29,25.74)
  VCC w0.203: 210.74,48.1 JHDD1.11 ; JHDD1.11 210.89,47.57 ; JHDD1.11 210.89,48.64 ; JHDD1.11 211.97,48.64 ; JHDD1.11 211.97,47.57 ; JHDD1.11 212.12,48.1 ; JUSB1.10 16.98,57.52 ; JUSB1.10 15.65,57.52 ; JUSB1.10 16.98,58.3 ; JUSB1.10 14.32,57.52 ; JUSB1.10 14.32,58.3 ; 209.8,71.82 H3.1 ; H3.1 208.38,72.33 ; H3.1 207.87,73.75 ; H3.1 209.8,75.68 ; H3.1 211.22,75.17 ; H3.1 211.73,73.75 ; H3.1 211.22,72.33 ; H3.1 208.38,75.17 ; JHDMI1.5 11.41,85.82 ; JHDMI1.5 11.41,86.74 ; JHDMI1.5 11.53,86.28 ; JODD1.12 225.36,110.15 ; JODD1.12 224.22,110.65 ; JODD1.12 225.5,110.65 ; JODD1.12 224.86,111.29 ; JODD1.12 224.86,110.01 ; JODD1.12 224.36,110.15 ; JODD1.12 225.36,111.15 ; JODD1.12 224.36,111.15 ; JODD1.13 226.36,112.15 ; JODD1.13 225.86,111.01 ; JODD1.13 226.36,111.15 ; JODD1.13 225.86,112.29 ; JODD1.13 226.5,111.65 ; JODD1.13 225.22,111.65 ; JODD1.13 225.36,112.15 ; JHDMI1.8 13.08,87.78 ; JHDMI1.8 11.91,87.78 ; JHDMI1.8 12.03,87.32 ; JHDMI1.8 12.03,88.24 ; JHDMI1.8 12.96,87.32 ; JHDMI1.8 12.96,88.24 ; 150.15,93.24 JWLAN1.50 ; JWLAN1.50 149.91,93.24 ; JWLAN1.50 150.39,93.24 ; H9.1 139.25,88.75 ; H9.1 139.89,90.45 ; H9.1 137.55,88.11 ; H9.1 139.25,92.15 ; H9.1 135.21,90.45 ; H9.1 135.85,88.75 ; H9.1 135.85,92.15 ; H9.1 137.55,92.79 ; 6.07,3.55 H7.1 ; H7.1 9.93,3.55 ; H7.1 9.42,4.97 ; H7.1 6.58,4.97 ; H7.1 6.58,2.13 ; H7.1 8,5.48 ; H7.1 8,1.62 ; H7.1 9.42,2.13 ; JHDD1.13 211.97,50.11 ; JHDD1.13 210.89,51.18 ; JHDD1.13 210.74,50.64 ; JHDD1.13 212.12,50.64 ; JHDD1.13 210.89,50.11 ; JHDD1.13 211.97,51.18 ; 6.4,43.37 JUSB1.12 ; JUSB1.12 7.58,43.37 ; JUSB1.12 5.22,43.37 ; JODD1.7 226.4,100.98 ; JODD1.7 226.4,99.9 ; JODD1.7 225.86,101.13 ; JODD1.7 226.55,100.44 ; JODD1.7 225.17,100.44 ; JODD1.7 225.32,100.98 ; JODD1.7 225.32,99.9 ; JUSB1.4 15.99,49.03 ; JUSB1.4 16.18,48.4 ; JUSB1.4 15.35,49.23 ; JUSB1.4 15.35,47.57 ; JUSB1.4 15.99,47.76 ; JUSB1.4 14.72,49.03 ; 210.89,29.79 JHDD1.1 ; JHDD1.1 211.97,30.86 ; JHDD1.1 212.12,30.32 ; JHDD1.1 211.43,29.64 ; JHDD1.1 210.74,30.32 ; JHDD1.1 210.89,30.86 ; JHDD1.1 211.97,29.79 ; 14.32,44.72 JUSB1.11 ; JUSB1.11 16.98,45.5 ; JUSB1.11 16.98,46.28 ; JUSB1.11 14.32,45.5 ; JUSB1.11 15.65,44.72 ; JUSB1.11 15.65,46.28 ; JUSB1.11 16.98,44.72 ; JUSB1.11 14.32,46.28 ; SW5.5 2.3,11.32 ; SW5.5 2.92,9.62 ; SW5.5 2.3,9.62 ; SW5.4 2.92,7.72 ; SW5.4 2.3,7.72 ; SW5.4 2.61,7.72 ; H1.1 213.2,114.08 ; H1.1 215.13,112.15 ; H1.1 211.27,112.15 ; H1.1 214.62,113.57 ; H1.1 214.62,110.73 ; H1.1 213.2,110.22 ; H1.1 211.78,110.73 ; H1.1 211.78,113.57 ; 210.89,48.84 JHDD1.12 ; JHDD1.12 210.74,49.37 ; JHDD1.12 211.97,48.84 ; JHDD1.12 212.12,49.37 ; JHDD1.12 210.89,49.91 ; JHDD1.12 211.97,49.91 ; 210.89,55.19 JHDD1.17 ; JHDD1.17 210.89,56.26 ; JHDD1.17 211.97,55.19 ; JHDD1.17 212.12,55.72 ; JHDD1.17 211.97,56.26 ; JHDD1.17 210.74,55.72 ; 12.7,25.67 JUSB2.5 ; JUSB2.5 13.98,25.67 ; JUSB2.5 13.98,27.33 ; JUSB2.5 11.42,25.67 ; JUSB2.5 13.98,26.5 ; JUSB2.5 12.7,27.33 ; JUSB2.5 11.42,27.33 ; JHDMI1.20 10.78,78.7 ; JHDMI1.20 9.5,78.7 ; JHDMI1.20 8.21,79.63 ; JHDMI1.20 10.78,79.63 ; 85.65,1.62 H5.1 ; H5.1 85.65,5.48 ; H5.1 83.72,3.55 ; H5.1 87.07,4.97 ; H5.1 87.07,2.13 ; H5.1 87.58,3.55 ; H5.1 84.23,4.97 ; H5.1 84.23,2.13 ; JHDD1.19 211.97,57.73 ; JHDD1.19 210.74,58.26 ; JHDD1.19 210.89,57.73 ; JHDD1.19 210.89,58.8 ; JHDD1.19 212.12,58.26 ; JHDD1.19 211.97,58.8 ; H6.1 24.64,12.37 ; H6.1 20.16,16.33 ; H6.1 24.64,16.33 ; H6.1 22.4,12.37 ; H6.1 22.4,16.33 ; H6.1 20.16,12.37 ; H6.1 20.16,14.35 ; H6.1 24.64,14.35 ; 153.91,93.24 JWLAN1.40 ; JWLAN1.40 154.39,93.24 ; JWLAN1.40 154.15,93.24 ; JUSB2.8 13.98,38.47 ; JUSB2.8 13.98,40.13 ; JUSB2.8 12.7,40.13 ; JUSB2.8 11.42,38.47 ; JUSB2.8 12.7,38.47 ; JUSB2.8 13.98,39.3 ; JUSB2.8 11.42,40.13 ; JODD1.4 226.4,97.17 ; JODD1.4 226.55,96.63 ; JODD1.4 225.32,96.09 ; JODD1.4 226.4,96.09 ; JODD1.4 225.32,97.17 ; JODD1.4 225.17,96.63 ; 80.05,88.75 H12.1 ; H12.1 84.09,90.45 ; H12.1 80.05,92.15 ; H12.1 83.45,88.75 ; H12.1 81.75,88.11 ; H12.1 79.41,90.45 ; H12.1 83.45,92.15 ; H12.1 81.75,92.79 ; JHDMI1.2 12.96,85.24 ; JHDMI1.2 12.03,85.24 ; JHDMI1.2 12.5,84.2 ; JHDMI1.2 12.03,84.32 ; JHDMI1.2 12.96,84.32 ; JHDMI1.2 13.08,84.78 ; JHDMI1.2 11.91,84.78 ; 23.3,53.92 H8.1 ; H8.1 24.72,57.27 ; H8.1 21.37,55.85 ; H8.1 21.88,54.43 ; H8.1 24.72,54.43 ; H8.1 23.3,57.78 ; H8.1 21.88,57.27 ; H8.1 25.23,55.85 ; JUSB1.7 14.49,52.53 ; JUSB1.7 13.85,51.07 ; JUSB1.7 14.68,51.9 ; JUSB1.7 13.85,52.73 ; JUSB1.7 14.49,51.26 ; JBATT1.10 194.05,100.03 ; JBATT1.10 194.05,98.02 ; JBATT1.10 193.35,98.02 ; JBATT1.10 192.66,100.03 ; JBATT1.10 192.66,99.03 ; JBATT1.10 193.35,100.03 ; JBATT1.10 192.66,98.02 ; JBATT1.10 194.05,99.03 ; 224.4,89.67 JODD1.14 ; JODD1.14 224.4,90.6 ; JODD1.14 224.4,91.53 ; JODD1.14 226.15,89.67 ; JODD1.14 226.15,91.53 ; H11.1 81.75,66.79 ; H11.1 84.09,64.45 ; H11.1 83.45,62.75 ; H11.1 80.05,62.75 ; H11.1 83.45,66.15 ; H11.1 80.05,66.15 ; H11.1 81.75,62.11 ; H11.1 79.41,64.45 ; JWLAN1.18 163.43,93.24 ; JWLAN1.18 163.43,94.18 ; JWLAN1.18 162.95,93.24 ; JBATT1.9 194.05,94.55 ; JBATT1.9 194.05,96.55 ; JBATT1.9 193.35,94.55 ; JBATT1.9 192.66,95.55 ; JBATT1.9 192.66,94.55 ; JBATT1.9 192.66,96.55 ; JBATT1.9 193.35,96.55 ; JBATT1.9 194.05,95.55 ; JHDD1.7 211.97,37.41 ; JHDD1.7 211.43,38.63 ; JHDD1.7 211.97,38.48 ; JHDD1.7 210.89,38.48 ; JHDD1.7 212.12,37.94 ; JHDD1.7 210.89,37.41 ; JHDD1.7 210.74,37.94 ; 208.38,4.97 H4.1 ; H4.1 211.22,4.97 ; H4.1 209.8,1.62 ; H4.1 211.73,3.55 ; H4.1 209.8,5.48 ; H4.1 208.38,2.13 ; H4.1 207.87,3.55 ; H4.1 211.22,2.13 ; JHDMI1.17 11.53,92.28 ; JHDMI1.17 11.41,92.74 ; JHDMI1.17 11.41,91.82 ; 211.73,67.1 JHDD1.23 ; JHDD1.23 209.98,67.1 ; JHDD1.23 211.73,68.93 ; JHDD1.23 213.48,68.93 ; JHDD1.23 209.98,68.93 ; JHDD1.23 209.98,68.01 ; JHDD1.23 213.48,68.01 ; JHDMI1.11 11.41,89.74 ; JHDMI1.11 11.41,88.82 ; JHDMI1.11 11.53,89.28 ; JUSB2.7 5.23,41.43 ; JUSB2.7 4.15,41.43 ; JUSB2.7 4.69,41.43 ; 8.21,98.86 JHDMI1.22 ; JHDMI1.22 9.5,98.86 ; JHDMI1.22 8.21,97.93 ; JHDMI1.22 10.78,98.86 ; JHDMI1.22 10.78,97.93 ; 217.18,110.73 H2.1 ; H2.1 218.6,110.22 ; H2.1 218.6,114.08 ; H2.1 220.02,110.73 ; H2.1 217.18,113.57 ; H2.1 220.53,112.15 ; H2.1 216.67,112.15 ; H2.1 220.02,113.57 ; 225.32,92.28 JODD1.1 ; JODD1.1 226.4,92.28 ; JODD1.1 225.86,92.13 ; JODD1.1 226.4,93.36 ; JODD1.1 225.17,92.82 ; JODD1.1 225.32,93.36 ; JODD1.1 226.55,92.82 ; 3.16,97.93 JHDMI1.23 ; JHDMI1.23 5.73,98.86 ; JHDMI1.23 5.73,97.93 ; JHDMI1.23 3.16,98.86 ; JHDMI1.23 4.45,98.86 ; JODD1.15 226.15,114.73 ; JODD1.15 224.4,113.8 ; JODD1.15 224.4,114.73 ; JODD1.15 224.4,112.87 ; JODD1.15 226.15,112.87 ; JHDD1.24 211.73,25.3 ; JHDD1.24 211.73,23.47 ; JHDD1.24 213.48,23.47 ; JHDD1.24 209.98,23.47 ; JHDD1.24 209.98,24.38 ; JHDD1.24 209.98,25.3 ; JHDD1.24 213.48,24.38 ; 204.91,94.55 JBATT1.11 ; JBATT1.11 205.6,94.55 ; JBATT1.11 204.91,96.55 ; JBATT1.11 206.3,96.55 ; JBATT1.11 206.3,95.55 ; JBATT1.11 206.3,94.55 ; JBATT1.11 204.91,95.55 ; JBATT1.11 205.6,96.55 ; JHDD1.4 211.97,34.67 ; JHDD1.4 210.89,33.6 ; JHDD1.4 210.74,34.13 ; JHDD1.4 212.12,34.13 ; JHDD1.4 210.89,34.67 ; JHDD1.4 211.97,33.6 ; 159.75,93.24 JWLAN1.26 ; JWLAN1.26 159.99,93.24 ; JWLAN1.26 159.51,93.24 ; JUSB2.4 13.11,30.11 ; JUSB2.4 12.4,30.33 ; JUSB2.4 13.33,29.4 ; JUSB2.4 11.69,28.69 ; JUSB2.4 13.11,28.69 ; JUSB2.4 11.47,29.4 ; JUSB2.4 11.69,30.11 ; JUSB2.4 12.4,28.47 ; JUSB2.6 5.23,24.37 ; JUSB2.6 3.07,24.37 ; JUSB2.6 4.15,24.37 ; JBATT1.12 206.3,100.03 ; JBATT1.12 204.91,99.03 ; JBATT1.12 206.3,99.03 ; JBATT1.12 204.91,100.03 ; JBATT1.12 204.91,98.02 ; JBATT1.12 206.3,98.02 ; JBATT1.12 205.6,100.03 ; JBATT1.12 205.6,98.02 ; 171.75,93.24 JWLAN1.4 ; JWLAN1.4 171.99,93.24 ; JWLAN1.4 171.51,93.24 ; JWLAN1.34 156.79,93.24 ; JWLAN1.34 156.31,93.24 ; JWLAN1.34 156.55,93.24 ; 3.16,79.63 JHDMI1.21 ; JHDMI1.21 3.16,78.7 ; JHDMI1.21 5.73,79.63 ; JHDMI1.21 4.45,78.7
  IN2 w0.381: v3(76.41,45.27) 76.26,45.27 69.54,51.98 69.54,59.72 68.36,60.91 68.36,66.2 77.53,75.37 94.01,75.37 v3(94.14,75.5)
  IN2 w0.508: v3(14.66,17.66) 12.35,17.66 v3(11.84,18.17) 11.84,18.68 14.38,21.22 14.38,22.61 16.04,24.27 16.04,25.54 15.65,25.92 v3(15.65,27.31)
  GND w0.203: JUSB2.7 5.23,40.6 ; JUSB2.7 4.15,41.43 ; JUSB2.7 3.07,40.6 ; JUSB2.7 3.07,41.43 ; JUSB2.7 5.23,41.43 ; 135.21,90.45 H9.1 ; H9.1 135.85,88.75 ; H9.1 137.55,92.79 ; H9.1 135.85,92.15 ; H9.1 139.89,90.45 ; H9.1 139.25,92.15 ; H9.1 139.25,88.75 ; H9.1 137.55,88.11 ; JHDD1.19 212.12,58.26 ; JHDD1.19 210.89,57.73 ; JHDD1.19 210.74,58.26 ; JHDD1.19 210.89,58.8 ; JHDD1.19 211.97,58.8 ; JHDD1.19 211.97,57.73 ; JUSB1.10 16.98,58.3 ; JUSB1.10 16.98,57.52 ; JUSB1.10 14.32,58.3 ; JUSB1.10 14.32,57.52 ; JUSB1.10 15.65,57.52 ; H11.1 84.09,64.45 ; H11.1 81.75,66.79 ; H11.1 79.41,64.45 ; H11.1 80.05,66.15 ; H11.1 81.75,62.11 ; H11.1 83.45,62.75 ; H11.1 80.05,62.75 ; H11.1 83.45,66.15 ; 210.89,47.57 JHDD1.11 ; JHDD1.11 212.12,48.1 ; JHDD1.11 210.74,48.1 ; JHDD1.11 210.89,48.64 ; JHDD1.11 211.97,48.64 ; JHDD1.11 211.97,47.57 ; 210.74,34.13 JHDD1.4 ; JHDD1.4 212.12,34.13 ; JHDD1.4 211.97,33.6 ; JHDD1.4 211.97,34.67 ; JHDD1.4 210.89,34.67 ; JHDD1.4 210.89,33.6 ; 11.69,28.69 JUSB2.4 ; JUSB2.4 13.33,29.4 ; JUSB2.4 11.69,30.11 ; JUSB2.4 13.11,28.69 ; JUSB2.4 11.47,29.4 ; JUSB2.4 13.11,30.11 ; JUSB2.4 12.4,28.47 ; JUSB2.4 12.4,30.33 ; 171.51,93.24 JWLAN1.4 ; JWLAN1.4 171.75,93.24 ; JWLAN1.4 171.75,95.12 ; 210.74,50.64 JHDD1.13 ; JHDD1.13 211.97,51.18 ; JHDD1.13 212.12,50.64 ; JHDD1.13 211.97,50.11 ; JHDD1.13 210.89,50.11 ; JHDD1.13 210.89,51.18 ; 192.66,98.02 JBATT1.10 ; JBATT1.10 194.05,99.03 ; JBATT1.10 194.05,100.03 ; JBATT1.10 193.35,98.02 ; JBATT1.10 192.66,100.03 ; JBATT1.10 192.66,99.03 ; JBATT1.10 193.35,100.03 ; JBATT1.10 194.05,98.02 ; JHDMI1.8 13.08,87.78 ; JHDMI1.8 12.03,87.32 ; JHDMI1.8 12.96,87.32 ; JHDMI1.8 11.91,87.78 ; JHDMI1.8 12.96,88.24 ; JHDMI1.8 12.03,88.24 ; JODD1.14 226.15,91.53 ; JODD1.14 226.15,89.67 ; JODD1.14 224.4,90.6 ; JODD1.14 227.9,89.67 ; JODD1.14 224.4,89.67 ; JODD1.14 224.4,91.53 ; JODD1.14 227.9,90.6 ; JODD1.14 227.9,91.53 ; 156.55,93.24 JWLAN1.34 ; JWLAN1.34 156.31,93.24 ; JWLAN1.34 156.55,95.12 ; JUSB2.8 13.98,40.13 ; JUSB2.8 13.98,38.47 ; JUSB2.8 12.7,38.47 ; JUSB2.8 11.42,40.13 ; JUSB2.8 11.42,38.47 ; JUSB2.8 13.98,39.3 ; JUSB2.8 12.7,40.13 ; JUSB2.8 11.42,39.3 ; JHDD1.24 213.48,25.3 ; JHDD1.24 209.98,25.3 ; JHDD1.24 213.48,23.47 ; JHDD1.24 211.73,23.47 ; JHDD1.24 213.48,24.38 ; JHDD1.24 209.98,23.47 ; JHDD1.24 211.73,25.3 ; JHDD1.24 209.98,24.38 ; 21.88,57.27 H8.1 ; H8.1 21.37,55.85 ; H8.1 24.72,57.27 ; H8.1 25.23,55.85 ; H8.1 23.3,57.78 ; H8.1 21.88,54.43 ; H8.1 23.3,53.92 ; H8.1 24.72,54.43 ; 211.78,113.57 H1.1 ; H1.1 211.27,112.15 ; H1.1 214.62,113.57 ; H1.1 211.78,110.73 ; H1.1 214.62,110.73 ; H1.1 213.2,114.08 ; H1.1 215.13,112.15 ; H1.1 213.2,110.22 ; 12.5,84.2 JHDMI1.2 ; JHDMI1.2 12.96,84.32 ; JHDMI1.2 11.91,84.78 ; JHDMI1.2 12.03,85.24 ; JHDMI1.2 13.08,84.78 ; JHDMI1.2 12.03,84.32 ; JHDMI1.2 12.96,85.24 ; 210.74,49.37 JHDD1.12 ; JHDD1.12 210.89,49.91 ; JHDD1.12 211.97,48.84 ; JHDD1.12 211.97,49.91 ; JHDD1.12 212.12,49.37 ; JHDD1.12 210.89,48.84 ; 13.22,51.26 JUSB1.7 ; JUSB1.7 13.85,51.07 ; JUSB1.7 14.49,51.26 ; JUSB1.7 13.85,52.73 ; JUSB1.7 13.22,52.53 ; JUSB1.7 14.68,51.9 ; JUSB1.7 14.49,52.53 ; JODD1.7 226.4,99.9 ; JODD1.7 226.4,100.98 ; JODD1.7 225.32,99.9 ; JODD1.7 225.32,100.98 ; JODD1.7 225.17,100.44 ; JODD1.7 225.86,101.13 ; JODD1.7 226.55,100.44 ; JODD1.1 226.4,93.36 ; JODD1.1 225.32,92.28 ; JODD1.1 226.4,92.28 ; JODD1.1 225.17,92.82 ; JODD1.1 225.86,92.13 ; JODD1.1 226.55,92.82 ; JODD1.1 225.32,93.36 ; SW5.5 2.3,11.32 ; SW5.5 2.3,9.62 ; SW5.5 2.92,9.62 ; SW5.5 1.68,9.62 ; SW5.5 1.68,11.32 ; SW5.5 1.68,10.47 ; 210.74,30.32 JHDD1.1 ; JHDD1.1 211.97,29.79 ; JHDD1.1 212.12,30.32 ; JHDD1.1 211.43,29.64 ; JHDD1.1 210.89,30.86 ; JHDD1.1 211.97,30.86 ; JHDD1.1 210.89,29.79 ; 3.16,98.86 JHDMI1.23 ; JHDMI1.23 3.16,97 ; JHDMI1.23 5.73,98.86 ; JHDMI1.23 3.16,97.93 ; JHDMI1.23 5.73,97 ; JHDMI1.23 5.73,97.93 ; JHDMI1.23 4.45,98.86 ; JHDMI1.23 4.45,97 ; H3.1 211.22,72.33 ; H3.1 209.8,75.68 ; H3.1 208.38,75.17 ; H3.1 211.73,73.75 ; H3.1 209.8,71.82 ; H3.1 211.22,75.17 ; H3.1 208.38,72.33 ; H3.1 207.87,73.75 ; H7.1 9.42,2.13 ; H7.1 8,1.62 ; H7.1 6.58,4.97 ; H7.1 9.93,3.55 ; H7.1 6.07,3.55 ; H7.1 9.42,4.97 ; H7.1 6.58,2.13 ; H7.1 8,5.48 ; 4.45,78.7 JHDMI1.21 ; JHDMI1.21 4.45,80.56 ; JHDMI1.21 3.16,79.63 ; JHDMI1.21 3.16,80.56 ; JHDMI1.21 5.73,79.63 ; JHDMI1.21 5.73,80.56 ; JHDMI1.21 3.16,78.7 ; 22.4,12.37 H6.1 ; H6.1 22.4,16.33 ; H6.1 20.16,14.35 ; H6.1 20.16,16.33 ; H6.1 24.64,14.35 ; H6.1 24.64,16.33 ; H6.1 20.16,12.37 ; H6.1 24.64,12.37 ; H10.1 139.89,64.45 ; H10.1 135.85,62.75 ; H10.1 137.55,62.11 ; H10.1 137.55,66.79 ; H10.1 139.25,66.15 ; H10.1 139.25,62.75 ; H10.1 135.21,64.45 ; H10.1 135.85,66.15 ; 210.89,37.41 JHDD1.7 ; JHDD1.7 210.89,38.48 ; JHDD1.7 211.97,38.48 ; JHDD1.7 212.12,37.94 ; JHDD1.7 211.43,38.63 ; JHDD1.7 210.74,37.94 ; JHDD1.7 211.97,37.41 ; JBATT1.9 194.05,95.55 ; JBATT1.9 194.05,94.55 ; JBATT1.9 192.66,94.55 ; JBATT1.9 192.66,95.55 ; JBATT1.9 193.35,96.55 ; JBATT1.9 193.35,94.55 ; JBATT1.9 192.66,96.55 ; JBATT1.9 194.05,96.55 ; JBATT1.11 206.3,96.55 ; JBATT1.11 204.91,95.55 ; JBATT1.11 204.91,96.55 ; JBATT1.11 206.3,95.55 ; JBATT1.11 206.3,94.55 ; JBATT1.11 204.91,94.55 ; JBATT1.11 205.6,96.55 ; JBATT1.11 205.6,94.55 ; JODD1.15 227.9,113.8 ; JODD1.15 226.15,112.87 ; JODD1.15 226.15,114.73 ; JODD1.15 224.4,113.8 ; JODD1.15 224.4,112.87 ; JODD1.15 224.4,114.73 ; JODD1.15 227.9,112.87 ; JHDMI1.20 10.78,79.63 ; JHDMI1.20 8.21,79.63 ; JHDMI1.20 9.5,80.56 ; JHDMI1.20 8.21,80.56 ; JHDMI1.20 10.78,80.56 ; JHDMI1.20 10.78,78.7 ; JHDMI1.20 9.5,78.7 ; SW5.4 2.3,7.72 ; SW5.4 2.3,6.02 ; SW5.4 2.92,7.72 ; SW5.4 1.68,7.72 ; SW5.4 1.68,6.87 ; 204.91,99.03 JBATT1.12 ; JBATT1.12 205.6,100.03 ; JBATT1.12 204.91,98.02 ; JBATT1.12 205.6,98.02 ; JBATT1.12 206.3,100.03 ; JBATT1.12 206.3,98.02 ; JBATT1.12 204.91,100.03 ; JBATT1.12 206.3,99.03 ; JUSB1.4 16.18,48.4 ; JUSB1.4 14.72,49.03 ; JUSB1.4 15.99,47.76 ; JUSB1.4 15.35,47.57 ; JUSB1.4 15.99,49.03 ; JUSB1.4 15.35,49.23 ; 150.15,93.24 JWLAN1.50 ; JWLAN1.50 149.91,93.24 ; JWLAN1.50 150.15,95.12 ; JHDMI1.22 10.78,97.93 ; JHDMI1.22 8.21,98.86 ; JHDMI1.22 9.5,98.86 ; JHDMI1.22 8.21,97.93 ; JHDMI1.22 9.5,97 ; JHDMI1.22 8.21,97 ; JHDMI1.22 10.78,97 ; JHDMI1.22 10.78,98.86 ; JUSB2.6 5.23,25.2 ; JUSB2.6 3.07,25.2 ; JUSB2.6 3.07,24.37 ; JUSB2.6 4.15,24.37 ; JUSB2.6 5.23,24.37 ; 225.86,111.01 JODD1.13 ; JODD1.13 225.22,111.65 ; JODD1.13 226.36,111.15 ; JODD1.13 226.5,111.65 ; JODD1.13 226.36,112.15 ; JODD1.13 225.86,112.29 ; JODD1.13 225.36,112.15 ; 217.18,113.57 H2.1 ; H2.1 218.6,110.22 ; H2.1 217.18,110.73 ; H2.1 218.6,114.08 ; H2.1 220.02,110.73 ; H2.1 220.53,112.15 ; H2.1 216.67,112.15 ; H2.1 220.02,113.57 ; JWLAN1.26 159.75,95.12 ; JWLAN1.26 159.51,93.24 ; JWLAN1.26 159.75,93.24 ; 162.95,93.24 JWLAN1.18 ; JWLAN1.18 162.95,95.12 ; JWLAN1.18 163.43,93.24 ; JWLAN1.18 163.43,94.18 ; JWLAN1.18 163.43,95.12 ; H4.1 211.73,3.55 ; H4.1 209.8,1.62 ; H4.1 211.22,4.97 ; H4.1 209.8,5.48 ; H4.1 207.87,3.55 ; H4.1 208.38,4.97 ; H4.1 211.22,2.13 ; H4.1 208.38,2.13 ; JODD1.4 226.4,97.17 ; JODD1.4 225.32,97.17 ; JODD1.4 225.17,96.63 ; JODD1.4 226.55,96.63 ; JODD1.4 225.32,96.09 ; JODD1.4 226.4,96.09 ; JUSB2.5 13.98,27.33 ; JUSB2.5 12.7,25.67 ; JUSB2.5 11.42,25.67 ; JUSB2.5 12.7,27.33 ; JUSB2.5 13.98,25.67 ; JUSB2.5 13.98,26.5 ; JUSB2.5 11.42,27.33 ; JUSB2.5 11.42,26.5 ; JODD1.12 225.36,111.15 ; JODD1.12 225.5,110.65 ; JODD1.12 224.22,110.65 ; JODD1.12 224.86,110.01 ; JODD1.12 224.36,111.15 ; JODD1.12 224.36,110.15 ; JODD1.12 224.86,111.29 ; JODD1.12 225.36,110.15 ; JHDMI1.5 11.41,85.82 ; JHDMI1.5 11.53,86.28 ; JHDMI1.5 11.41,86.74 ; 209.98,67.1 JHDD1.23 ; JHDD1.23 209.98,68.93 ; JHDD1.23 213.48,67.1 ; JHDD1.23 211.73,67.1 ; JHDD1.23 213.48,68.93 ; JHDD1.23 209.98,68.01 ; JHDD1.23 211.73,68.93 ; JHDD1.23 213.48,68.01 ; 84.23,4.97 H5.1 ; H5.1 87.07,2.13 ; H5.1 83.72,3.55 ; H5.1 85.65,5.48 ; H5.1 84.23,2.13 ; H5.1 87.07,4.97 ; H5.1 87.58,3.55 ; H5.1 85.65,1.62 ; JHDMI1.11 11.41,88.82 ; JHDMI1.11 11.53,89.28 ; JHDMI1.11 11.41,89.74 ; 5.22,44.2 JUSB1.12 ; JUSB1.12 5.22,43.37 ; JUSB1.12 6.4,43.37 ; JUSB1.12 7.58,44.2 ; JUSB1.12 7.58,43.37 ; 210.74,55.72 JHDD1.17 ; JHDD1.17 211.97,55.19 ; JHDD1.17 210.89,55.19 ; JHDD1.17 211.97,56.26 ; JHDD1.17 210.89,56.26 ; JHDD1.17 212.12,55.72 ; 15.65,44.72 JUSB1.11 ; JUSB1.11 14.32,44.72 ; JUSB1.11 15.65,46.28 ; JUSB1.11 14.32,45.5 ; JUSB1.11 16.98,45.5 ; JUSB1.11 16.98,46.28 ; JUSB1.11 14.32,46.28 ; JUSB1.11 16.98,44.72 ; JHDMI1.17 11.53,92.28 ; JHDMI1.17 11.41,92.74 ; JHDMI1.17 11.41,91.82 ; H12.1 83.45,92.15 ; H12.1 81.75,88.11 ; H12.1 79.41,90.45 ; H12.1 81.75,92.79 ; H12.1 80.05,88.75 ; H12.1 83.45,88.75 ; H12.1 84.09,90.45 ; H12.1 80.05,92.15 ; 153.91,93.24 JWLAN1.40 ; JWLAN1.40 154.15,95.12 ; JWLAN1.40 154.15,93.24
  BOTTOM w0.127: v3(48.16,65.72) v2(47.52,65.72)
  BOTTOM w0.203: v3(122.43,77.11) 122.09,77.45 121.47,77.45 UC4.BJ27
  BOTTOM w0.229: v3(96.2,77.33) 96.27,77.33 96.39,77.45 97.83,77.45 UC4.A27 ; UC4.A23 97.83,79.4 96.96,79.4 v3(96.96,79.39)
  BOTTOM w0.254: UC4.BJ11 121.47,85.22 122.01,85.22 v3(122.23,85.44) ; UC4.A49 97.8,66.46 97.66,66.32 97.54,66.32 97.44,66.22 v3(97.28,66.22) ; UC4.AE1 109.27,90.26 v3(109.16,90.37) ; UC4.A19 97.51,81.66 v3(96.98,81.66) ; v3(101.99,82.22) 101.99,82.41 UC4.J16 ; UC4.C49 99.01,67.31 v3(98.91,67.41) ; UC4.AB45 UC4.AB47 UC4.AB48 UC4.AB50 108.2,65.73 UC4.AB51 108.44,65.72 v3(108.79,66.07) ; UC4.C42 98.92,69.98 99.14,69.75 99.14,69.39 98.62,68.87 UC4.C45 99,68.75 v3(99.11,68.64) ; QM1.4 172.23,86.52 172.48,86.52 v3(172.75,86.24) ; UC4.G42 101.29,70.52 v3(101.29,70.6) 101.61,70.92 UC4.J40 ; UC4.A11 97.26,85.22 v3(97.19,85.15) ; v3(108.39,48.47) 108.13,48.21 107.86,48.21 107.33,47.69 JDIMM1.127 ; UC4.A15 97.54,83.58 v3(97.14,83.58) ; v3(97.19,67.92) 97.28,67.83 UC4.A47 ; UC4.A35 97.33,73.56 v3(97.28,73.51) ; UC4.BF4 120.26,88.61 v3(120.33,88.54) ; QM1.1 171.23,88.51 v3(171.02,88.72) ; UC4.E53 99.66,64.63 99.66,64.41 99.08,63.83 v3(98.72,63.83) ; UC4.AH3 111.25,89.18 UC4.AJ3 111.47,89.52 UC4.AH2 111.21,89.88 UC4.AJ1 111.59,90.45 v3(111.34,90.71) ; UC4.A43 97.44,69.68 v3(97.28,69.83) ; UC4.P52 104.18,65.02 UC4.N51 103.67,65.38 UC4.M51 103.09,65.72 v3(102.77,66.04) 102.61,66.2 102.45,66.2 UC4.K50 ; UC4.AJ21 v3(111.23,80.86) ; v3(109.84,64.1) 109.65,64.28 109.65,64.63 UC4.AE53 ; UC4.AJ53 111.94,64.64 v3(112.1,64.48) ; UC4.BJ23 121.74,79.11 v3(121.95,79.11) ; UC4.AA53 107.71,64.63 107.71,64.29 107.62,64.19 v3(107.62,63.9) ; UC4.Y25 106.95,78.21 v3(107.31,77.85) ; UC4.BJ15 122.19,83.28 122.26,83.35 v3(122.26,83.37) ; 118.27,90.26 118.27,89.93 UC4.BC2 ; UC4.AT12 115.24,84.82 v3(115.55,84.82) ; JDIMM1.133 109.13,45.15 108.29,44.3 v3(107.91,44.3) ; UC4.J53 101.88,64.63 101.88,63.84 v3(101.94,63.78) ; v3(113.57,76.26) 113.57,76.33 113.21,76.69 UC4.AM29 ; UC4.P47 104.31,67.69 103.93,67.69 v3(103.82,67.8) 103.72,67.69 103.33,67.69 UC4.M47 ; UC4.BJ35 122.01,73.56 v3(122.06,73.51) ; JDIMM1.195 127.73,45.07 v3(127.7,45.04) ; v3(122.21,87) 122.14,87.07 UC4.BJ7 ; v3(111.56,88.45) 111.43,88.59 UC4.AH4 ; UC4.BJ19 121.47,81.34 122.1,81.34 v3(122.29,81.14)
  BOTTOM w0.305: v3(116.15,44.18) 115.73,44.59 JDIMM1.155 ; JDIMM1.26 74.63,40.09 v3(74.03,40.69) ; CC36.1 91.22,65.16 90.43,65.95 v3(90.43,66.05) ; v3(73.29,44.71) 73.57,44.71 74.33,45.48 JDIMM1.25 ; JDIMM1.184 124.43,39.47 124.75,39.79 124.75,40.34 124.42,40.67 v3(124.24,40.67) ; v3(102.88,84.7) 102.88,84.34 UC4.L13 102.74,84.19 UC4.K14 ; v3(71.42,44.55) 71.96,44.55 72.32,44.91 72.32,45.65 72.53,45.86 JDIMM1.19 ; v3(113.33,43.98) 113.11,43.98 112.81,44.28 112.81,44.8 112.91,44.9 112.91,45.63 112.73,45.81 JDIMM1.145 ; JDIMM1.151 114.53,44.1 115.87,42.77 v3(116.52,42.77) ; v3(125.81,45.05) 125.93,45.16 JDIMM1.189 ; v3(78.19,44.4) 78.21,44.4 78.54,44.73 78.54,45.24 77.93,45.85 JDIMM1.37 ; 118.27,90.26 UC4.BC1 118.27,90.63 v3(118.42,90.78) ; v3(72.29,40.91) 72.65,40.91 73.01,40.55 73.01,39.9 72.83,39.73 JDIMM1.20 ; v3(101.46,59.63) 101.05,59.63 100.62,59.19 CC35.1 ; JDIMM1.9 69.53,45.73 69.3,45.49 69.3,45.14 69.8,44.64 v3(70.02,44.64) ; JDIMM1.138 110.63,40.3 110.9,40.56 v3(111.29,40.56) ; JDIMM1.61 85.13,45.51 86.14,44.5 v3(86.34,44.5) 86.59,44.5 86.83,44.74 86.83,45.37 86.53,45.67 86.52,45.67 86.33,45.86 JDIMM1.65
  BOTTOM w0.356: JDIMM1.2 67.43,39.51 v3(66.71,40.24) ; JDIMM1.44 80.03,40.19 v3(80.63,40.79) 81.23,40.19 JDIMM1.48 ; JDIMM1.144 112.43,39.88 112.4,39.91 112.4,39.93 v3(112.27,40.06) ; v3(67.72,45.12) 67.73,45.12 JDIMM1.3 ; JDIMM1.43 79.73,45.84 79.97,45.61 79.97,44.96 79.67,44.67 v3(79.38,44.67) ; JDIMM1.66 v3(86.63,40.24) ; JDIMM1.190 126.23,40 v3(125.91,40.32) ; JDIMM1.185 124.73,44.83 124.23,44.33 v3(124.11,44.33) ; JDIMM1.128 107.63,39.79 v3(107.75,39.91) ; JDIMM1.71 88.13,45.92 88.3,45.75 v3(88.3,45.39) ; JDIMM1.161 117.53,45.73 117.71,45.55 117.71,44.89 117.35,44.53 117.23,44.53 v3(117.2,44.51) ; v3(108.85,40.57) 109.05,40.57 109.43,40.19 JDIMM1.134 ; JDIMM1.162 117.83,40.27 117.56,40.54 v3(117.3,40.54) ; JDIMM1.150 114.23,39.71 114.49,39.96 v3(114.56,39.96) ; v3(84.26,40.54) 84.46,40.54 84.83,40.17 JDIMM1.60 ; JDIMM1.55 83.33,45.85 83.52,45.66 83.52,45.36 84,44.88 v3(84,44.53) ; v3(127.56,40.7) 128.12,40.13 128.12,39.55 128.03,39.46 JDIMM1.196 ; JDIMM1.167 119.33,45.09 118.92,44.68 118.89,44.68 v3(118.76,44.55) ; JDIMM1.38 78.23,40.35 77.98,40.59 v3(77.61,40.59) ; JDIMM1.31 76.13,45.55 v3(76.41,45.27) ; JDIMM1.179 122.93,45.6 123.12,45.41 123.12,44.86 122.64,44.38 v3(122.43,44.38) ; JDIMM1.14 71.03,40.67 70.78,40.92 v3(70.44,40.92) ; JDIMM1.13 70.73,45.84 70.54,45.65 70.54,45.62 70.54,45.62 70.54,45.17 70.23,44.86 v3(70.02,44.64) ; JDIMM1.72 88.43,39.35 88.77,39.68 v3(88.91,39.68) ; JDIMM1.139 110.93,45.32 111.64,44.61 v3(111.94,44.61) ; v3(122.82,39.91) 122.63,39.72 JDIMM1.178 ; v3(121.58,40.7) 120.83,39.95 JDIMM1.172 ; v3(120.35,40.69) 119.92,40.26 119.92,39.91 119.63,39.63 JDIMM1.168 ; JDIMM1.8 69.23,39.6 68.99,39.84 68.99,40.99 v3(67.61,42.37) ; v3(76.89,41.71) 76.43,41.25 JDIMM1.32 ; JDIMM1.54 83.03,39.46 83.16,39.58 83.16,40.14 v3(82.44,40.86) ; JDIMM1.156 v3(116.03,39.96) ; v3(121.44,44.82) 121.13,45.13 JDIMM1.173 ; v3(80.97,44.67) 80.99,44.68 80.99,44.97 81.53,45.51 JDIMM1.49
  BOTTOM w0.381: v3(94.47,82.17) 94.36,82.05 CC49.2 92.95,82.05 CC47.2 ; DY1.3 14.32,91.3 13.89,91.73 v3(13.89,91.81) ; PR216.2 PC212.2 202.66,75.64 v3(202.93,75.9) ; v3(15.92,85.87) DY2.3 ; v3(156.75,90.09) 156.15,90.69 JWLAN1.35 ; v3(126.81,74.43) 126.81,74.05 126.56,73.8 CC88.1 ; v3(94.14,75.5) 93.56,74.92 RC15.2 ; v3(19.67,48.89) 19.68,48.87 DS1.3 ; PC209.2 197.7,75.24 v3(197.33,74.88) 197.84,74.37 PC210.2 ; DY3.3 16.03,81.69 v3(16.02,81.68) ; CY9.2 15.73,95.05 v3(15.27,95.51) ; CC19.2 92.14,89.39 91.96,89.57 v3(91.96,89.65) ; v3(96.98,81.66) 96.96,81.64 CC61.2
  BOTTOM w0.508: CS3.1 v3(20.71,39.89) ; CL10.2 CL1.1 v3(34.07,61.67) ; YL1.4 35.92,61.4 v3(34.91,60.38) ; JSB1.5 189.3,57 189.03,57.26 v3(188.7,57.26) ; CX11.2 55.79,89.16 v3(56.29,88.65) ; PC313.2 192.47,43.11 v3(192.91,43.56) 193.36,43.11 PR308.2 ; v3(48.83,98.74) PC101.2 PC100.2 ; PC733.1 v3(158.52,67.36) ; v3(63.24,32.16) 65.46,32.16 65.98,31.64 JDIMM1.205 64.31,30.65 v3(63.79,31.17) ; PC311.2 v3(186.25,41.78) ; v3(148.96,62.58) PC752.1 149.67,62.57 PR732.1 ; PC320.2 49.32,47.32 v3(48.67,46.66) ; CL16.1 v3(35.57,62.67) ; RL3.2 v3(41.76,69.51) ; v3(49.1,83.89) 50.3,82.69 CX13.2 ; v3(38.61,44.33) 38.77,44.48 PC327.2 ; CC45.2 v3(120.05,97.27) ; PC744.2 155,56.86 154.65,56.51 v3(154.45,56.51) ; v3(95.28,92.22) 95.28,93.58 UC9.3 ; v3(104.1,93.86) 103.97,93.73 CC48.2 ; CC12.2 111.51,94.23 111.92,93.81 v3(112.07,93.81) ; v3(169.45,90.48) 169.75,90.78 JWLAN1.9 ; v3(200.26,77.17) 200.38,77.06 PC207.1 ; v3(41.76,67.35) CL6.2 41.05,66.29 CL4.2 ; RL6.1 34.1,63.11 34.1,62.45 v3(34.11,62.45) ; v3(198.58,9.56) 198.58,9.56 C12.2 198.58,7.68 v3(198.58,7.68) ; CC27.2 v3(126.49,83.24) ; JSD1.3 49.17,18.34 48.75,17.92 v3(48.19,17.92) ; v3(64.36,9.41) 64.34,9.39 RB31.1 ; CL15.2 28.03,59.45 27.84,59.27 ; v3(11.84,18.17) 12.35,17.66 DA5.1 ; v3(129.1,30.65) JDIMM1.206 133.32,30.65 v3(134.12,29.85) ; v3(182.92,95.49) JSPK1.3 182.72,98.18 v3(181.21,98.18) ; CX12.2 56.22,89.75 v3(56.55,89.42) ; v3(162.66,62.58) 162.65,62.58 PC724.2 162,62.57 PR707.2 ; v3(204.14,81.37) 204.15,81.37 PC105.2 ; CA18.1 29.62,18.17 30.08,17.71 v3(30.06,17.71) ; PC415.2 154.69,36.71 v3(155.13,37.15) 155.58,36.71 PR409.2 ; CC17.2 93.48,92.36 93.13,92.7 93.13,93.17 v3(93.12,93.18) ; JSD1.6 v3(41.67,20.88) ; PC768.1 127.57,71.33 v3(126.73,70.49) ; v3(153.37,58.79) 153.22,58.64 PR727.2 ; v3(37.24,58.07) 37.65,58.48 YL1.2 ; RX8.1 CX14.1 50.2,92.9 50.48,92.62 50.48,92.61 50.7,92.39 50.71,92.39 50.73,92.36 v3(50.73,92.21) ; v3(204.2,80.35) 205.24,81.39 PC104.2 ; JSD1.13 v3(60.12,2.55) ; CC25.2 v3(93.77,88.29) ; PR303.2 189.75,43.3 v3(190.08,43.62) ; JEDP1.5 v3(56.9,95.61) ; v3(53.88,92.59) 53.5,92.97 RX5.2 52.94,92.97 CX15.1 ; JSB1.8 190.53,60.9 v3(189.95,61.48) ; JEDP1.23 v3(65.9,95.57) ; RC64.1 96.93,95.51 v3(96.68,95.77) ; CC15.2 125.99,88.91 v3(126.32,89.24) ; RC19.2 v3(126.26,79.6) ; v3(31.38,4.38) JSD1.12 v3(29.47,2.55) ; CA28.2 190.13,91.01 ; v3(190.25,15.12) JRTC1.2 190.78,17.85 v3(192.08,16.54) ; v3(61.01,79.33) 61.13,79.33 61.5,78.96 UC6.3 ; v3(189.8,49.62) 190.28,50.1 JSB1.7 193.81,50.1 v3(193.99,49.92) ; v3(30.77,65.49) 30.27,65.98 DL2.2 ; JEDP1.14 60.9,99.8 59.86,98.76 v3(59.72,98.76) ; CC52.1 97.9,93.25 97.29,92.65 v3(97.29,91.98) ; JEDP1.6 v3(56.9,98.99) ; v3(52.51,90.52) 52.7,90.33 QX1.3 ; v3(107.81,95.83) 107.92,95.72 YC1.2 ; 155.34,88.92 155.35,88.93 JWLAN1.37 ; RL5.1 v3(16.8,79.76) ; JEDP1.11 v3(59.9,95.69) ; v3(88.31,69.09) 88.22,69.17 CC67.2 ; CC39.2 126.14,92.97 v3(126.4,93.23) ; UC5.3 57.13,78.85 57.28,79 CC2.1 57.94,78.64 v3(57.46,78.16) ; PC408.1 154.5,26.74 v3(154.01,26.25) ; PR200.1 39.86,90.1 v3(40.47,90.71) ; QB1.3 68.33,8.16 v3(67.98,8.52) ; v3(16.28,93.13) 15.73,93.68 CY11.1 ; v3(189.87,95.82) JSPK1.4 188.73,97.97 v3(188.53,98.18) ; v3(161.27,90.08) 161.75,90.56 JWLAN1.21 ; PC762.1 v3(149.66,57.37) ; JWLAN1.27 v3(159.35,90.09) ; CC13.2 108.62,94.25 v3(109.13,93.73) ; v3(32.52,73.26) 31.83,72.58 CL9.2 32.47,71.71 v3(32.47,71.69) ; RX4.2 59.6,88.35 v3(59.72,88.48) ; RL7.1 v3(15.91,79.89) ; v3(186.1,87.69) DA4.1 ; v3(58.32,45.25) 57.85,44.78 CLRP1.2 CLRP2.2 ; PR313.2 v3(37.75,44.35) ; JBATT1.8 v3(195.1,94.16) ; CA29.2 v3(183.41,91.01) ; CB12.2 89.77,80.45 v3(89.19,80.45) ; PC402.2 v3(141.29,25.74) ; JWLAN1.15 167.35,92.65 v3(167.72,93.02) ; J1.1 26.62,89.74 v3(26.32,89.44) ; CC78.1 v3(126.4,91.22) ; CS5.2 v3(20.38,36.74) ; CC18.2 91.96,92.11 v3(91.96,92.1) ; JSB1.6 189.72,58 189.06,58.66 v3(188.7,58.66) ; US1.2 v3(17.43,40.06) ; v3(126.4,71.23) 126.4,71.12 QC1.3 ; CL13.1 v3(37.01,62.69) ; JEDP1.17 v3(62.9,95.64) ; DS2.2 v3(20.42,44.06) ; JWLAN1.29 v3(158.55,90.09) ; v3(91.38,87.05) 91.03,87.4 CC24.2 ; PC738.2 v3(154.51,68.03) ; DS3.2 v3(14.82,35.37) ; JP1.4 v3(195.67,4.59) ; CX10.1 50.07,85.17 v3(50.07,84.77) ; v3(22,31.25) 22.21,31.25 22.77,30.69 RA31.2 ; CC87.1 126.49,69.6 v3(126.5,69.6) ; CC21.2 91.97,94.86 v3(91.97,95.29) ; PC223.2 v3(197.19,65.48) ; CC4.1 CC3.1 61.7,82.3 v3(62.09,82.69) ; v3(25.94,26.12) 26.5,26.68 CA6.2 27.29,26.68 27.26,26.71 CA5.2 ; v3(196.36,94.92) 196.35,94.91 JBATT1.7 ; CC53.1 v3(100.59,92.74) ; JWLAN1.43 152.95,90.89 152.12,90.05 v3(151.86,90.05) ; PC325.2 v3(46.59,50.66) ; PC705.2 v3(162.02,57.27) ; CC28.2 v3(126.49,84.18) ; YC1.4 v3(109.99,97.42) ; PR225.2 v3(197.21,67.26) ; v3(66.23,90.46) 65.92,90.76 CX1.2 65.92,92.29 v3(66.25,92.62) ; PC222.2 202.18,66.38 v3(202.19,66.37)
  BOTTOM w1.016: v3(31.43,27.54) 34.58,27.54 35.49,26.63 55.73,26.63 57.01,25.35 59.72,25.35 63.72,21.35 63.72,16.76 65.71,14.77 69.07,14.77 69.86,13.98 76.41,13.98 v3(76.94,13.44) 79.18,13.44 80.04,14.31 98.39,14.31 102.78,9.91 111.42,9.91 v3(113.42,7.92) 115.51,5.83 163.22,5.83 v3(167.22,9.83) v3(176.41,19.02) 176.41,26.15 170.86,31.7 v3(170.86,39.81) v3(170.86,54.39) 170.86,77.21 181.03,87.38 181.03,89.8 182.24,91.01 v3(183.41,91.01) ; 190.13,91.01 191.12,90.02 191.12,84.18 188.25,81.31 v3(184.87,81.31) 183.79,81.31 182.89,82.2 181.24,82.2 174.67,75.63 v3(174.67,54.36) 174.67,33.75 180.22,28.2 v3(180.22,17.39) v3(172.31,9.47) 164.85,2.02 112.86,2.02 v3(111.41,3.46) 111.41,4.05 109.35,6.1 v3(109.2,6.1) 101.2,6.1 96.81,10.5 83.35,10.5 v3(82.84,9.99) 81.11,9.99 80.66,9.53 74.93,9.53 74.29,10.17 68.28,10.17 67.49,10.96 64.13,10.96 59.83,15.26 59.83,16.31 59.83,16.31 59.83,19.85 58.14,21.54 55.43,21.54 54.16,22.82 48.88,22.82 ; JUSB1.13 10.72,59.6 11.45,60.33 14.39,60.33 15.65,59.07 JUSB1.10
  vias: v2(12.57,41.84) v2(15.22,9.3) v2(16.66,78.98) v2(17.98,8.48) v2(30.14,11.52) v2(32.24,79.98) v2(33.23,61.88) v2(36.1,80.16) v2(38.22,3.6) v2(67.84,2.5) v2(79.19,97.67) v2(87.16,98.65) v2(90.27,9.41) v2(90.89,91.38) v2(93.82,3.33) v2(106.01,87.14) v2(110.37,96.22) v2(113.1,60.57) v2(117.17,80.96) v2(121.78,58.03) v2(129.14,92.58) v2(135.87,5.92) v2(142.34,86.43) v2(155.71,63.18) v2(160.07,69.47) v2(169.41,15.05) v2(175.09,4.05) v2(177.81,72.18) v2(179.84,93.14) v2(180.22,86.87) v2(180.83,76.07) v2(182.42,59.25) v2(184.97,64.45) v2(186.86,82.25) v2(194.19,28.47) v2(201.35,26.8) v2(202.43,63.94) v2(207.9,19.46) v3(1.71,97.04) v3(1.71,80.52) v3(1.71,25.59) v3(1.96,101.2) v3(2.17,5.5) v3(2.65,77.21) v3(2.81,44.59) v3(2.81,40.21) v3(4.83,4.05) v3(5.27,1.79) v3(5.75,5.9) v3(6.31,24.62) v3(6.56,42.35) v3(8.14,6.69) v3(9.03,40.21) v3(9.03,25.59) v3(9.33,0.62) v3(10.32,42.35) v3(10.32,24.55) v3(10.57,1.56) v3(10.7,96.94) v3(10.81,95.16) v3(10.81,82.4) v3(10.75,80.65) v3(10.91,39.7) v3(10.91,32.9) v3(10.91,26.1) v3(10.88,5.37) v3(11.31,44.59) v3(11.29,2.9) v3(12.46,98.24) v3(13.09,79.83) v3(13.31,44.8) v3(13.85,29.4) v3(14.21,42.5) v3(14.18,33.61) v3(15.12,31.1) v3(15.76,10.42) v3(15.96,43.85) v3(16.82,47.13) v3(16.76,0.5) v3(17.91,98.43) v3(18.87,58.09) v3(19.28,0.5) v3(20.73,10.09) v3(22.03,83.73) v3(22.05,85.61) v3(22.13,79.51) v3(22.51,81.54) v3(22.56,99.02) v3(23.12,26.12) v3(23.2,24.47) v3(23.2,22.77) v3(23.5,97.87) v3(24.03,10.08) v3(24.07,68.36) v3(24.24,97.87) v3(24.24,72.1) v3(24.22,64.85) v3(24.8,26.12) v3(24.77,24.48) v3(24.8,22.95) v3(24.95,97.87) v3(25.03,86.04) v3(25.31,81.68) v3(25.52,0.5) v3(25.81,88.65) v3(25.94,24.47) v3(25.94,22.95) v3(26.37,101.94) v3(26.88,81.97) v3(27.34,44.94) v3(27.46,39.91) v3(27.57,46.39) v3(27.74,43.82) v3(28.03,0.5) v3(28.1,39.91) v3(28.3,99.83) v3(28.48,43.82) v3(28.63,51.29) v3(28.79,36.41) v3(28.79,35.24) v3(29,47.1) v3(29.8,52.71) v3(31.36,97.32) v3(31.8,101.94) v3(32.4,99.79) v3(32.98,15.1) v3(33.16,0.5) v3(35.03,68.72) v3(35.08,69.46) v3(35.12,67.81) v3(35.31,72.7) v3(35.67,68.75) v3(35.82,69.65) v3(35.82,67.85) v3(35.85,3.36) v3(36.54,67.79) v3(36.68,69.78) v3(36.68,68.61) v3(37.1,98.24) v3(37.24,101.94) v3(37.84,98.24) v3(38.29,0.5) v3(38.49,94.71) v3(38.55,98.19) v3(38.66,72.27) v3(38.96,95.3) v3(39.1,94.71) v3(39.54,39.07) v3(39.57,95.3) v3(39.58,38.43) v3(39.62,3.33) v3(39.73,47.73) v3(40.39,47.71) v3(40.93,46.12) v3(40.93,45.45) v3(40.98,44.79) v3(41.51,47.74) v3(41.57,46.13) v3(41.56,45.45) v3(41.64,44.8) v3(42.15,94.55) v3(42.22,46.13) v3(42.2,45.45) v3(42.35,47.73) v3(42.5,72.3) v3(42.67,101.94) v3(42.91,46.12) v3(42.88,45.45) v3(43.38,51.15) v3(43.42,17.57) v3(43.41,0.5) v3(43.47,22.79) v3(44.05,51.15) v3(44.23,22.74) v3(44.61,16.47) v3(46.54,14.36) v3(46.54,12.58) v3(47.43,13.48) v3(47.66,82.94) v3(47.68,17.05) v3(48.1,101.94) v3(48.32,14.38) v3(48.32,12.58) v3(48.54,0.5) v3(49.72,17.46) v3(50.63,37.58) v3(50.58,36.84) v3(50.68,40.85) v3(50.71,40.21) v3(52.23,68.46) v3(52.2,67.48) v3(52.23,66.65) v3(52.46,100.94) v3(53.07,100.94) v3(53.54,101.94) v3(53.7,100.94) v3(53.67,0.5) v3(56.28,81.54) v3(56.42,63.23) v3(56.89,81.54) v3(57.61,63.2) v3(58.4,60.76) v3(58.79,0.5) v3(58.97,101.94) v3(58.98,63.2) v3(59.26,60.76) v3(59.6,90.05) v3(60.33,63.25) v3(61.5,89.36) v3(62.52,60.63) v3(62.49,59.85) v3(63.46,89.79) v3(63.45,2.55) v3(63.92,0.5) v3(64.05,73.59) v3(64.41,101.94) v3(64.4,74.12) v3(67.16,41.51) v3(67.27,70.94) v3(67.9,70.92) v3(68.56,97.8) v3(69.05,0.5) v3(69.17,97.82) v3(69.61,83.19) v3(69.84,101.94) v3(69.78,97.82) v3(70.27,83.2) v3(71.53,41.65) v3(72.55,92.54) v3(73.39,95.89) v3(74.03,42.22) v3(74.18,0.5) v3(74.57,88.78) v3(75.27,101.94) v3(75.4,40.72) v3(75.8,100.94) v3(76.05,99.01) v3(76.26,43.16) v3(76.46,100.94) v3(76.71,99.01) v3(77.1,100.95) v3(77.32,99.01) v3(78.09,43.13) v3(78.21,96.03) v3(78.87,40.54) v3(79.3,0.5) v3(82.35,2.73) v3(82.53,44.8) v3(83.97,43.21) v3(84.21,71.07) v3(84.43,0.5) v3(84.49,81.92) v3(85.12,81.92) v3(86.9,42.25) v3(87.23,0.59) v3(87.64,93.02) v3(87.69,91.65) v3(87.66,40.64) v3(88.25,43.75) v3(88.68,2.14) v3(88.91,66.22) v3(89.49,65.18) v3(90.13,101.94) v3(90.25,0.52) v3(93.45,67.19) v3(94.55,95.31) v3(94.68,0.5) v3(95.67,101.94) v3(97.14,75.6) v3(97.34,90.1) v3(97.3,88.78) v3(97.32,71.64) v3(97.67,64.35) v3(98.2,59.66) v3(99.14,85.2) v3(99.09,72.57) v3(99.27,81.36) v3(99.81,0.5) v3(100.46,76.48) v3(100.57,78.44) v3(100.67,89.14) v3(100.74,86.29) v3(100.67,79.41) v3(100.8,88.47) v3(100.79,87.66) v3(101.2,101.94) v3(101.46,40.95) v3(101.69,90.75) v3(101.89,88.93) v3(101.89,86.9) v3(101.94,79.46) v3(102.05,49.82) v3(102.65,76.48) v3(102.69,78.4) v3(103.31,74.45) v3(103.8,88.28) v3(103.77,87.69) v3(103.81,86.82) v3(104.1,79.48) v3(104.78,88.32) v3(104.81,87.56) v3(104.78,86.8) v3(104.81,84.61) v3(104.86,75.47) v3(104.94,0.5) v3(105.77,71.42) v3(106.48,77.81) v3(106.74,101.94) v3(106.73,87.45) v3(106.73,86.71) v3(106.69,86.06) v3(106.76,85.37) v3(106.89,97.29) v3(107.68,86.9) v3(107.7,86.16) v3(107.65,84.69) v3(107.73,70.27) v3(107.75,85.5) v3(108.66,86.9) v3(108.69,86.14) v3(108.85,80.88) v3(108.8,42.55) v3(108.87,82.43) v3(108.87,81.63) v3(109.66,78.58) v3(109.86,61.17) v3(110.06,0.5) v3(110.42,72.57) v3(110.65,84.79) v3(111.23,41.84) v3(111.51,87.51) v3(111.49,86.85) v3(111.62,70.09) v3(112,77.83) v3(112,76.26) v3(112.02,72.57) v3(112.27,101.94) v3(112.4,96.73) v3(112.6,86.84) v3(112.59,69.47) v3(112.6,68.79) v3(112.78,74.74) v3(112.83,73.28) v3(113.52,96.71) v3(113.57,79.33) v3(113.7,71.72) v3(113.88,60.66) v3(114.45,88.9) v3(114.54,68) v3(114.49,66.71) v3(114.58,82.35) v3(115.19,0.5) v3(115.27,74.57) v3(115.48,67.47) v3(115.63,94.27) v3(115.57,90.83) v3(115.55,65.97) v3(116.4,86.91) v3(116.39,84.66) v3(116.39,66) v3(116.52,86.09) v3(116.47,68.79) v3(116.47,66.94) v3(116.61,82.22) v3(116.62,76.53) v3(116.57,75.49) v3(116.74,94.27) v3(116.74,85.35) v3(116.82,96.78) v3(116.8,78.39) v3(116.95,64.27) v3(117.1,91.37) v3(117.23,80.32) v3(117.34,76.49) v3(117.35,75.43) v3(117.33,72.72) v3(117.31,71.59) v3(117.4,95.29) v3(117.43,88.85) v3(117.35,82.22) v3(117.35,79.31) v3(117.48,88.22) v3(117.48,87.51) v3(117.5,86.89) v3(117.52,78.4) v3(117.81,101.94) v3(117.96,82.25) v3(118.1,80.44) v3(118.19,79.43) v3(118.25,78.41) v3(118.16,70.58) v3(118.29,84.28) v3(118.55,86.27) v3(118.53,83.3) v3(118.75,80.47) v3(118.84,78.46) v3(118.84,70.6) v3(118.8,68.39) v3(119.13,40.65) v3(119.39,67.47) v3(119.54,83.31) v3(119.57,84.31) v3(120.12,70.62) v3(120.3,90.79) v3(120.32,0.5) v3(120.48,69.2) v3(120.76,63.94) v3(121.09,91.27) v3(121.72,64.47) v3(121.72,59.55) v3(122,69.6) v3(122.15,89.71) v3(122.1,88.62) v3(122.11,67.75) v3(122.08,66.3) v3(122.18,59.11) v3(122.56,68.13) v3(123.35,101.94) v3(125.44,0.5) v3(125.92,42.5) v3(126.25,58.84) v3(126.42,66.18) v3(126.42,64.4) v3(126.4,63.71) v3(126.4,63) v3(126.83,68.56) v3(126.8,58.58) v3(127.67,42.1) v3(128.46,43.16) v3(128.88,101.94) v3(130.57,0.5) v3(130.74,79.26) v3(131.4,82.08) v3(131.38,81.16) v3(131.35,80.1) v3(134.09,74.86) v3(134.22,82.02) v3(134.42,101.94) v3(134.7,74.86) v3(134.83,82.05) v3(134.83,69.8) v3(135.31,74.86) v3(135.67,69.86) v3(135.7,0.5) v3(135.77,82) v3(136.1,74.83) v3(136.38,82.02) v3(136.71,74.83) v3(137.32,82.02) v3(137.5,74.86) v3(137.93,82.05) v3(138.11,74.86) v3(138.94,82.68) v3(138.97,84.16) v3(139.02,74.88) v3(139.63,74.88) v3(139.96,101.94) v3(140.04,98.71) v3(140.11,70.24) v3(140.09,69.52) v3(140.16,70.92) v3(140.82,0.5) v3(141.17,100.54) v3(142.2,98.71) v3(142.6,84.08) v3(142.63,83.39) v3(142.78,41.6) v3(144.12,41.6) v3(144.93,75.37) v3(144.94,63.08) v3(144.94,62.49) v3(144.91,26.36) v3(144.97,27.5) v3(145.29,26.93) v3(145.44,41.6) v3(145.49,101.94) v3(145.47,96.45) v3(145.52,63.08) v3(145.52,62.49) v3(145.61,75.34) v3(145.61,26.36) v3(145.67,27.5) v3(145.99,26.93) v3(145.95,0.5) v3(146.27,75.34) v3(146.31,26.36) v3(146.37,27.5) v3(146.69,26.93) v3(146.84,41.6) v3(146.88,75.34) v3(147,26.36) v3(147.07,27.5) v3(147.39,26.93) v3(147.7,26.36) v3(147.77,27.5) v3(148.08,26.93) v3(148.19,41.63) v3(148.4,26.36) v3(149.51,41.63) v3(150.48,79.74) v3(150.48,78.97) v3(151.14,79.8) v3(151.14,79.15) v3(151.08,0.5) v3(151.17,78.29) v3(151.18,77.63) v3(151.18,76.98) v3(151.85,78.29) v3(151.87,77.63) v3(151.87,76.98) v3(152.53,78.3) v3(152.54,77.64) v3(152.54,76.98) v3(152.53,37.03) v3(152.53,36.39) v3(152.53,35.31) v3(152.53,34.68) v3(152.92,28.55) v3(153.14,29.1) v3(153.27,31.84) v3(153.29,31.12) v3(153.99,31.82) v3(153.99,31.12) v3(154.21,69.19) v3(154.26,88.79) v3(154.38,77.98) v3(154.57,78.8) v3(154.83,88.64) v3(154.92,69.17) v3(154.89,62.96) v3(154.93,61.08) v3(155.05,80.35) v3(155.01,78.27) v3(155.18,79.13) v3(155.33,79.76) v3(155.69,78.26) v3(155.79,78.9) v3(155.85,62.07) v3(155.96,79.79) v3(156.2,0.5) v3(156.35,78.49) v3(156.35,77.77) v3(156.35,79.21) v3(156.64,79.81) v3(156.65,69.17) v3(156.69,63.04) v3(156.75,61.06) v3(157.36,69.19) v3(157.98,79.04) v3(157.98,78.4) v3(157.97,77.75) v3(158.35,71.61) v3(158.35,71.03) v3(161.33,0.5) v3(161.6,69.88) v3(161.68,72.01) v3(161.68,71.35) v3(161.68,70.69) v3(163.38,72.42) v3(163.41,71.69) v3(163.41,70.93) v3(163.41,70.21) v3(163.88,94.34) v3(166.46,0.5) v3(171.59,0.5) v3(175.09,89.98) v3(175.67,90.05) v3(176.71,0.5) v3(176.81,101.94) v3(176.89,96.4) v3(177.02,33.74) v3(177.17,37.42) v3(177.33,92.5) v3(177.61,34.75) v3(177.71,35.72) v3(179.18,50.78) v3(180.14,95.15) v3(180.41,99.74) v3(180.47,56.45) v3(180.5,54.43) v3(181.3,79.99) v3(181.84,0.5) v3(182.59,101.94) v3(185.35,100.72) v3(185.44,97.31) v3(185.64,65.03) v3(186.34,65.03) v3(186.32,60.54) v3(186.39,58.05) v3(186.9,37.9) v3(186.9,37.14) v3(186.97,0.5) v3(187.48,99.05) v3(187.49,65.1) v3(188.18,65.1) v3(188.37,101.94) v3(188.51,26.37) v3(188.51,24.39) v3(188.88,65.1) v3(189.58,65.1) v3(190.22,36.22) v3(190.22,35.56) v3(190.22,34.9) v3(190.2,34.24) v3(190.2,33.58) v3(190.28,65.1) v3(190.98,65.1) v3(191.68,65.1) v3(191.68,55.89) v3(191.83,36.88) v3(191.83,36.19) v3(191.83,35.51) v3(191.83,34.83) v3(192.09,0.5) v3(192.37,65.1) v3(192.51,56.07) v3(192.51,36.91) v3(192.54,36.2) v3(192.51,35.49) v3(192.49,34.8) v3(193.16,35.56) v3(193.16,34.87) v3(193.73,35.24) v3(193.89,60.99) v3(194.14,101.94) v3(194.74,59.76) v3(194.72,58.84) v3(194.75,57.82) v3(194.99,95.67) v3(194.97,94.99) v3(195.64,96) v3(195.61,95.32) v3(195.56,62.06) v3(195.69,59.75) v3(195.7,58.82) v3(195.69,57.79) v3(196.63,58.81) v3(196.69,59.76) v3(196.68,57.82) v3(196.81,99.41) v3(197.22,0.5) v3(197.33,68.97) v3(197.33,68.37) v3(197.34,44.02) v3(197.81,79.38) v3(197.8,78.72) v3(197.97,44.02) v3(198.68,44) v3(198.81,32.79) v3(199.32,44) v3(199.45,32.81) v3(199.61,71.57) v3(199.61,70.21) v3(199.73,97.68) v3(199.92,101.94) v3(200.11,43.95) v3(200.38,70.75) v3(200.76,71.57) v3(200.77,43.92) v3(201.14,70.21) v3(202.17,99.47) v3(202.35,0.5) v3(205.7,101.94) v3(206.36,42.16) v3(206.71,4.2) v3(207.03,43.18) v3(207,42.44) v3(207.03,41.79) v3(207.6,97.29) v3(207.63,1.15) v3(207.68,71.26) v3(207.68,43.15) v3(207.65,42.49) v3(207.72,41.8) v3(207.88,76.49) v3(207.88,60.42) v3(207.89,59.72) v3(207.87,59.04) v3(208.14,6.54) v3(208.21,114.15) v3(208.21,104.45) v3(208.29,63.4) v3(208.35,61.12) v3(208.44,80.79) v3(208.54,59.01) v3(208.54,10.69) v3(208.55,60.38) v3(208.55,59.72) v3(208.8,98.77) v3(208.8,95.81) v3(208.96,108.17) v3(208.97,101.35) v3(209.89,70.44) v3(209.96,112.28) v3(210.26,90.98) v3(210.29,0.49) v3(210.5,76.97) v3(210.83,109.66) v3(210.85,105.9) v3(210.83,6.66) v3(210.98,114.64) v3(211.16,21.18) v3(211.44,16.76) v3(211.62,12.98) v3(211.56,8.74) v3(212.02,71.28) v3(212.61,1.79) v3(212.8,75.02) v3(212.89,108.9) v3(212.94,73.06) v3(212.92,66.2) v3(212.92,60.49) v3(212.92,54.77) v3(212.92,49.06) v3(212.92,43.34) v3(212.92,37.63) v3(212.92,31.91) v3(212.92,26.2) v3(212.91,4.66) v3(213.11,80.48) v3(213.46,115.4) v3(214.09,67.21) v3(214.05,24.98) v3(214.09,19.09) v3(214.09,13) v3(214.09,6.9) v3(214.41,93.99) v3(214.76,100.19) v3(215.39,105.87) v3(215.46,96.69) v3(216.1,79.02) v3(216.99,93.91) v3(216.99,93.15) v3(217.05,103.86) v3(218.04,108.9) v3(217.98,98.6) v3(217.98,97.41) v3(218.14,115.39) v3(218.18,80.63) v3(218.47,105.83) v3(220.25,114.74) v3(220.3,109.15) v3(221.06,99.37) v3(221.6,113.93) v3(221.72,111.41) v3(221.7,89.1) v3(221.72,84.3) v3(221.66,81.82) v3(221.76,86.88) v3(221.88,80.3) v3(223.34,90.47) v3(223.41,87.73) v3(223.64,115.4) v3(224.35,112.32) v3(225.29,83.07) v3(226.57,85.93) v3(226.61,81.33) v3(226.91,115.32) v3(227.91,108.93) v3(227.9,103.75) v3(227.9,98.55) v3(227.91,93.77) v3(227.9,88.15) v3(227.9,83.33)
